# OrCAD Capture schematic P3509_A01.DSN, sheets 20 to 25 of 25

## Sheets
20 0005_SODIMM Connector 2_3: size Custom
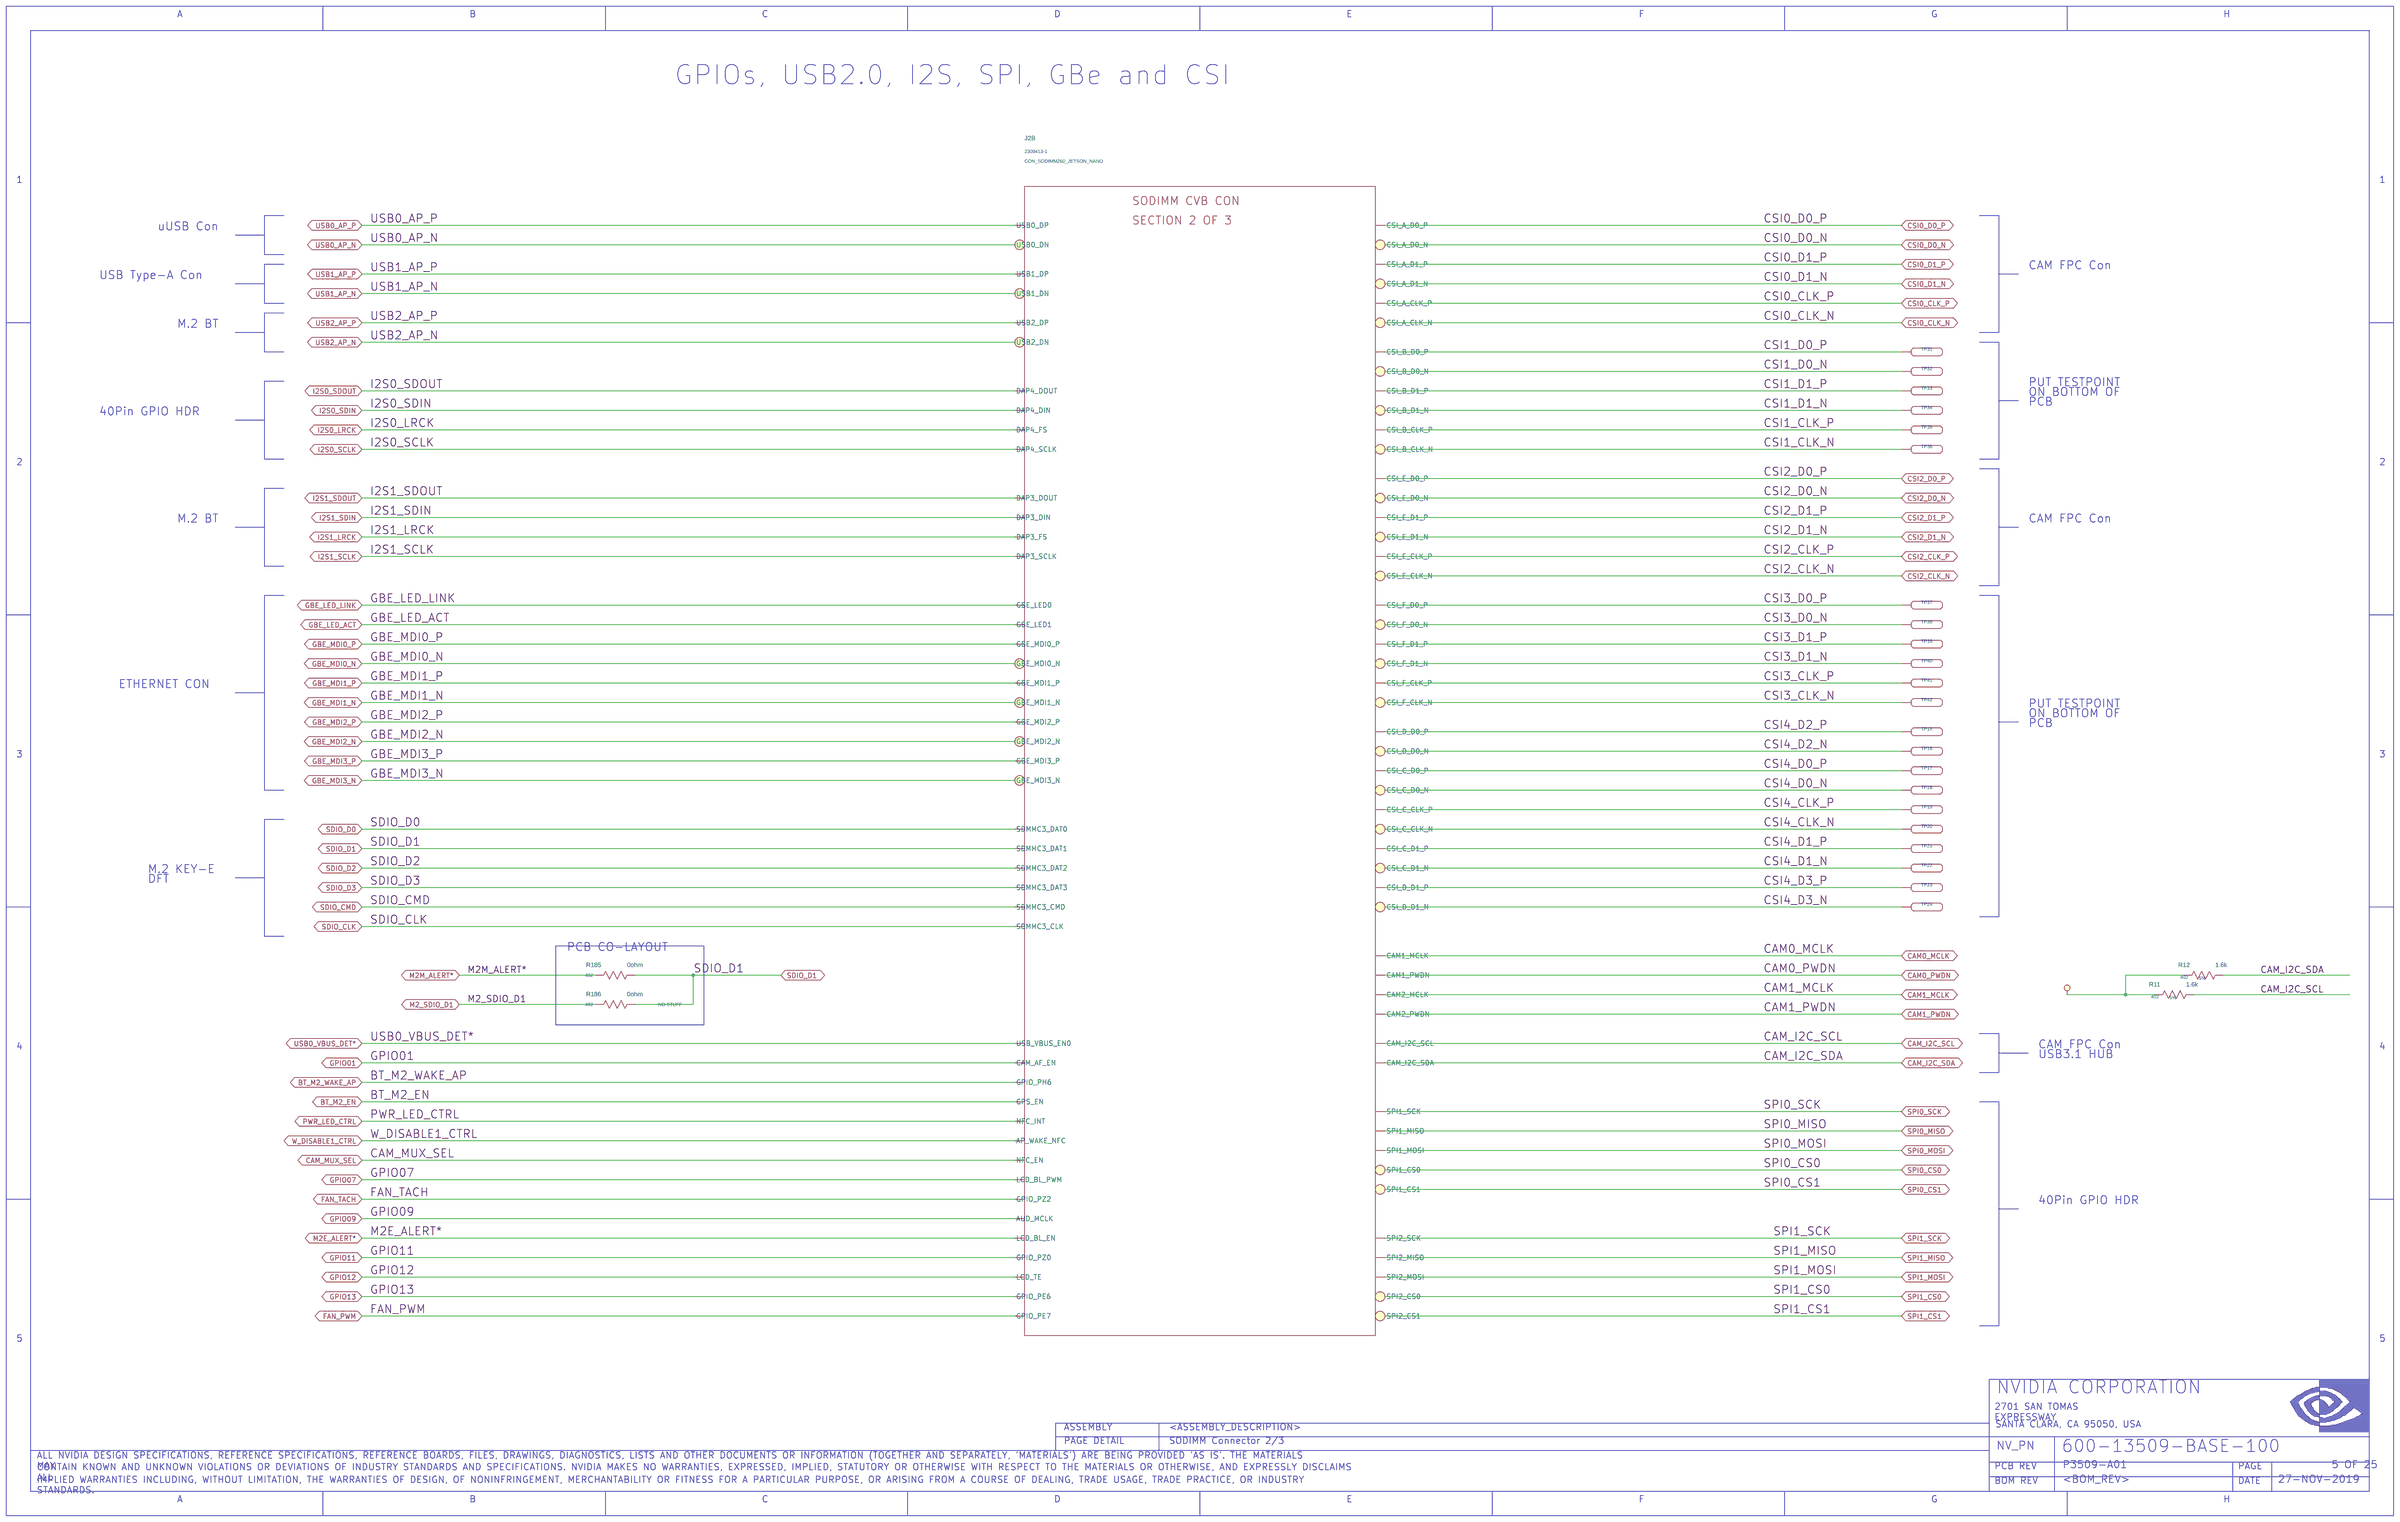
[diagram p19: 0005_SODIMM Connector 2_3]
21 0004_SODIMM Connector 1_3: size Custom
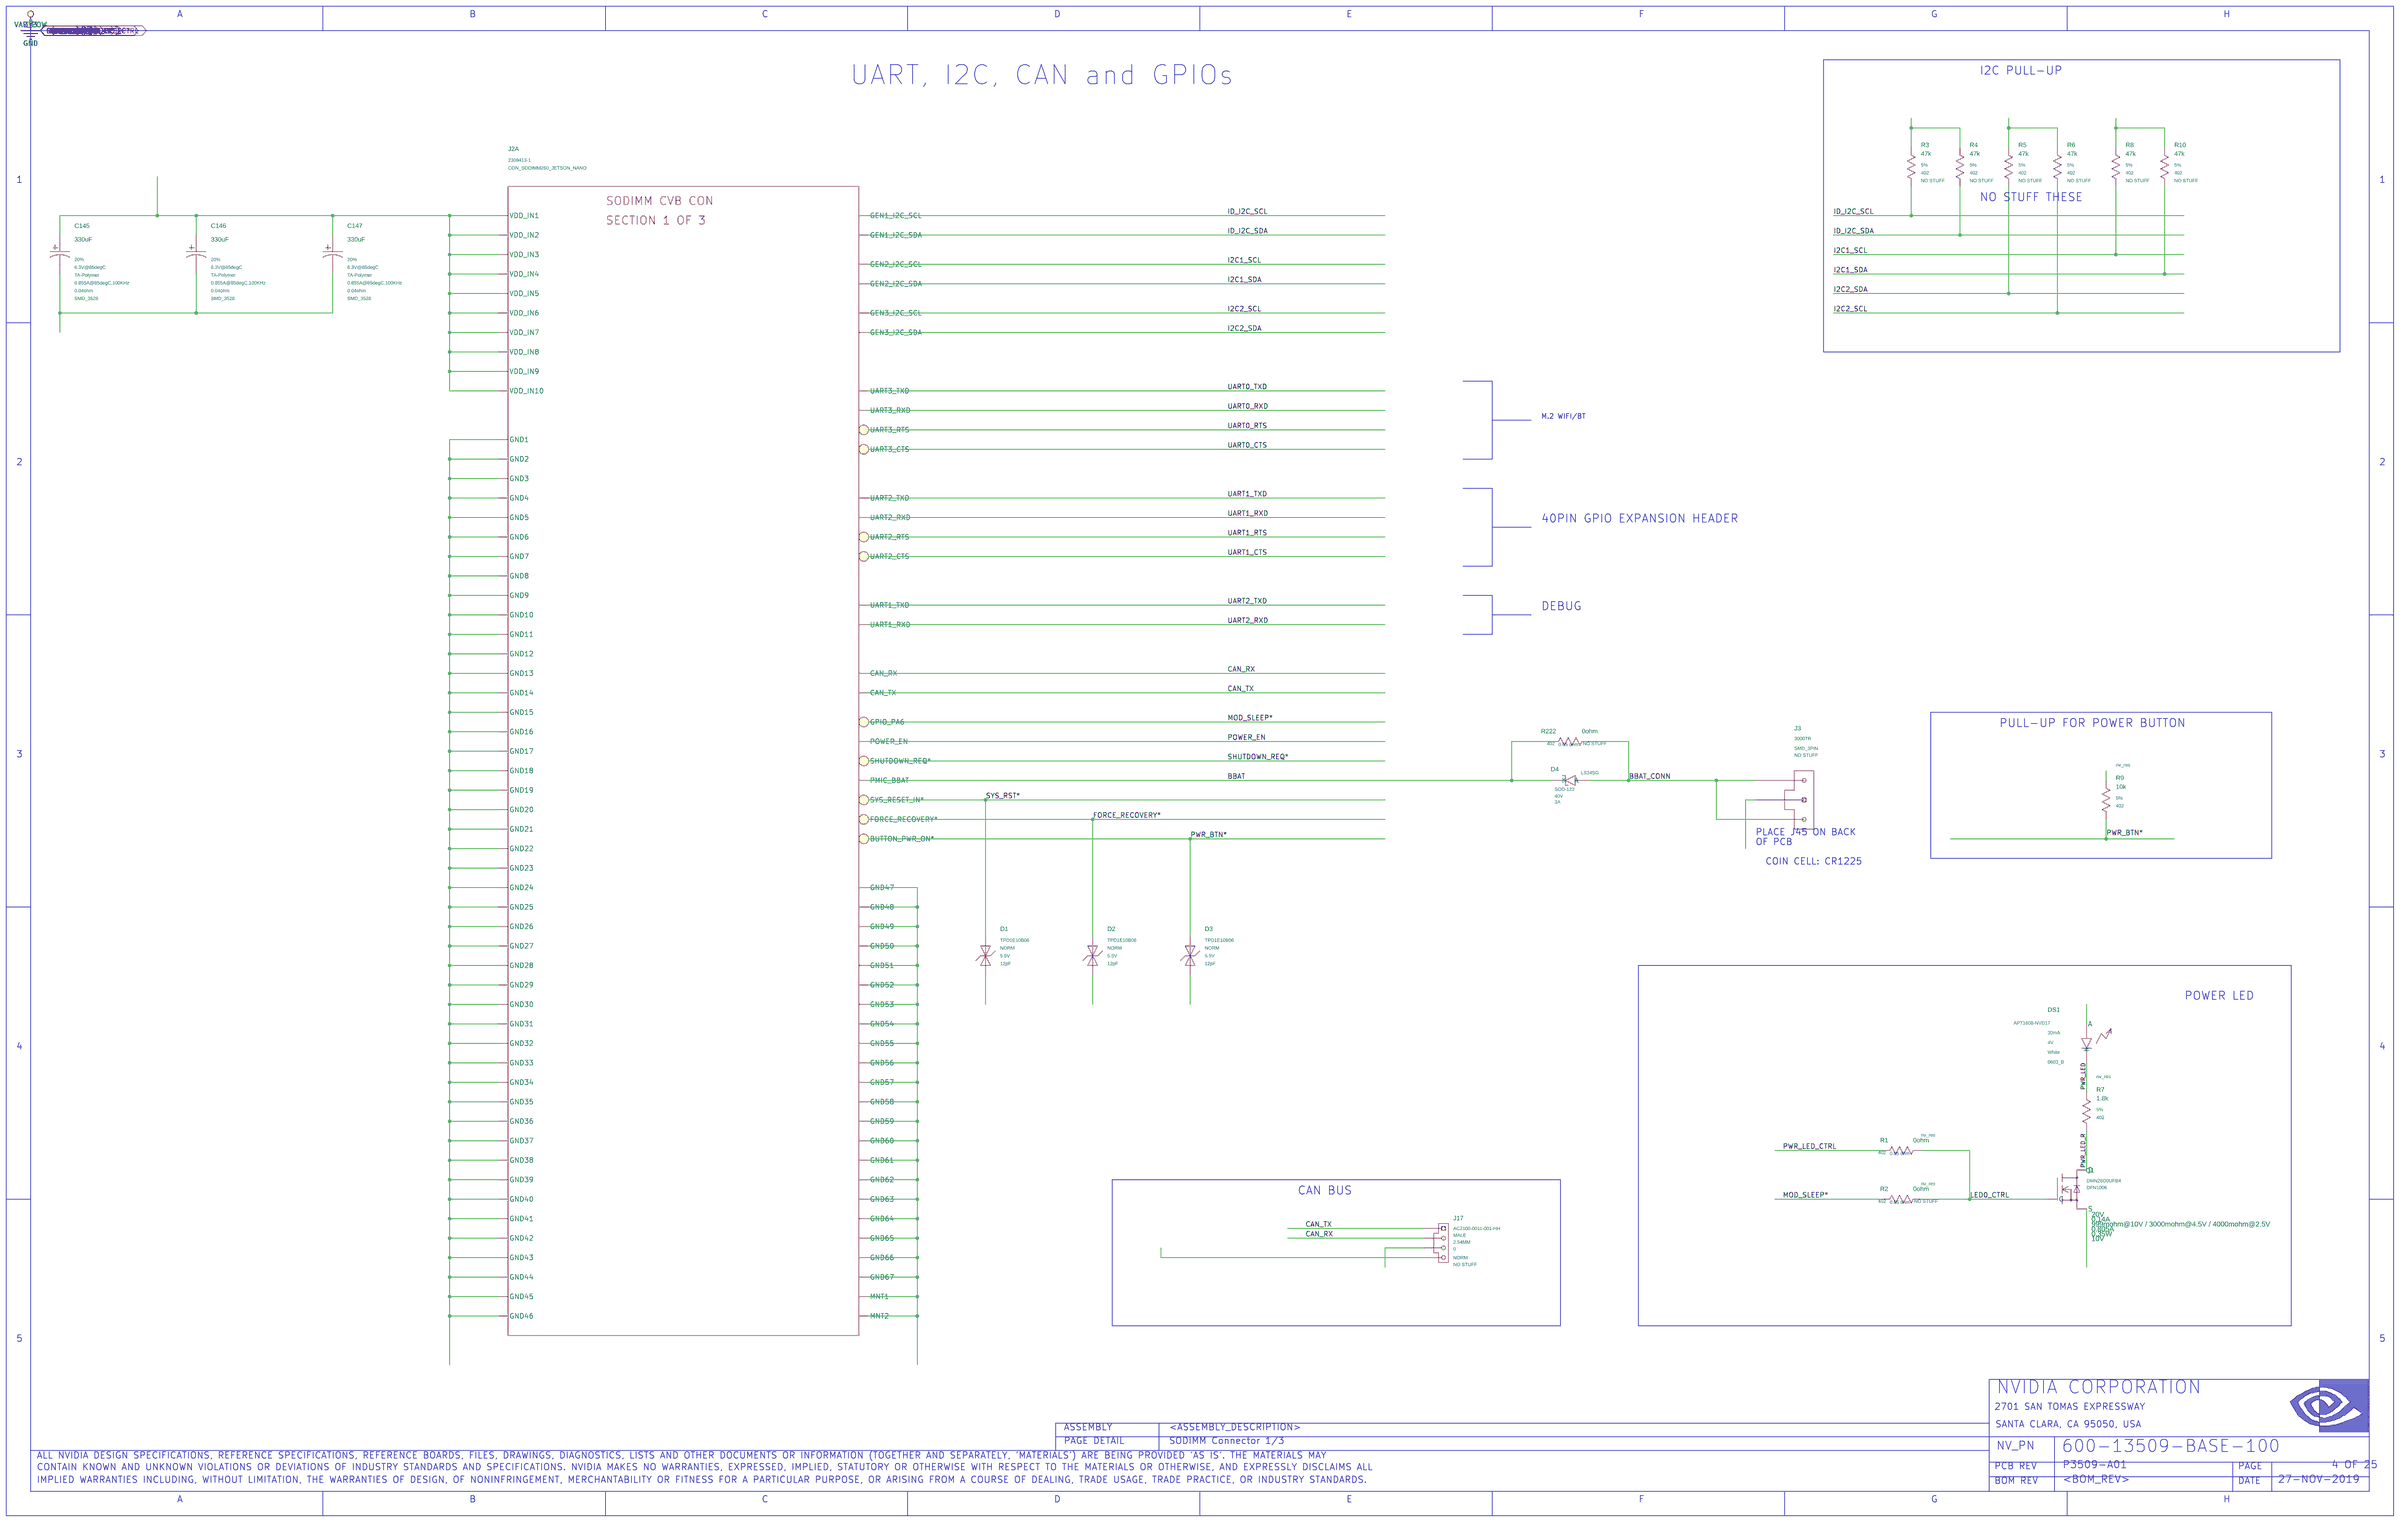
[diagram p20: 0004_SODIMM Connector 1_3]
22 0003_Power Tree
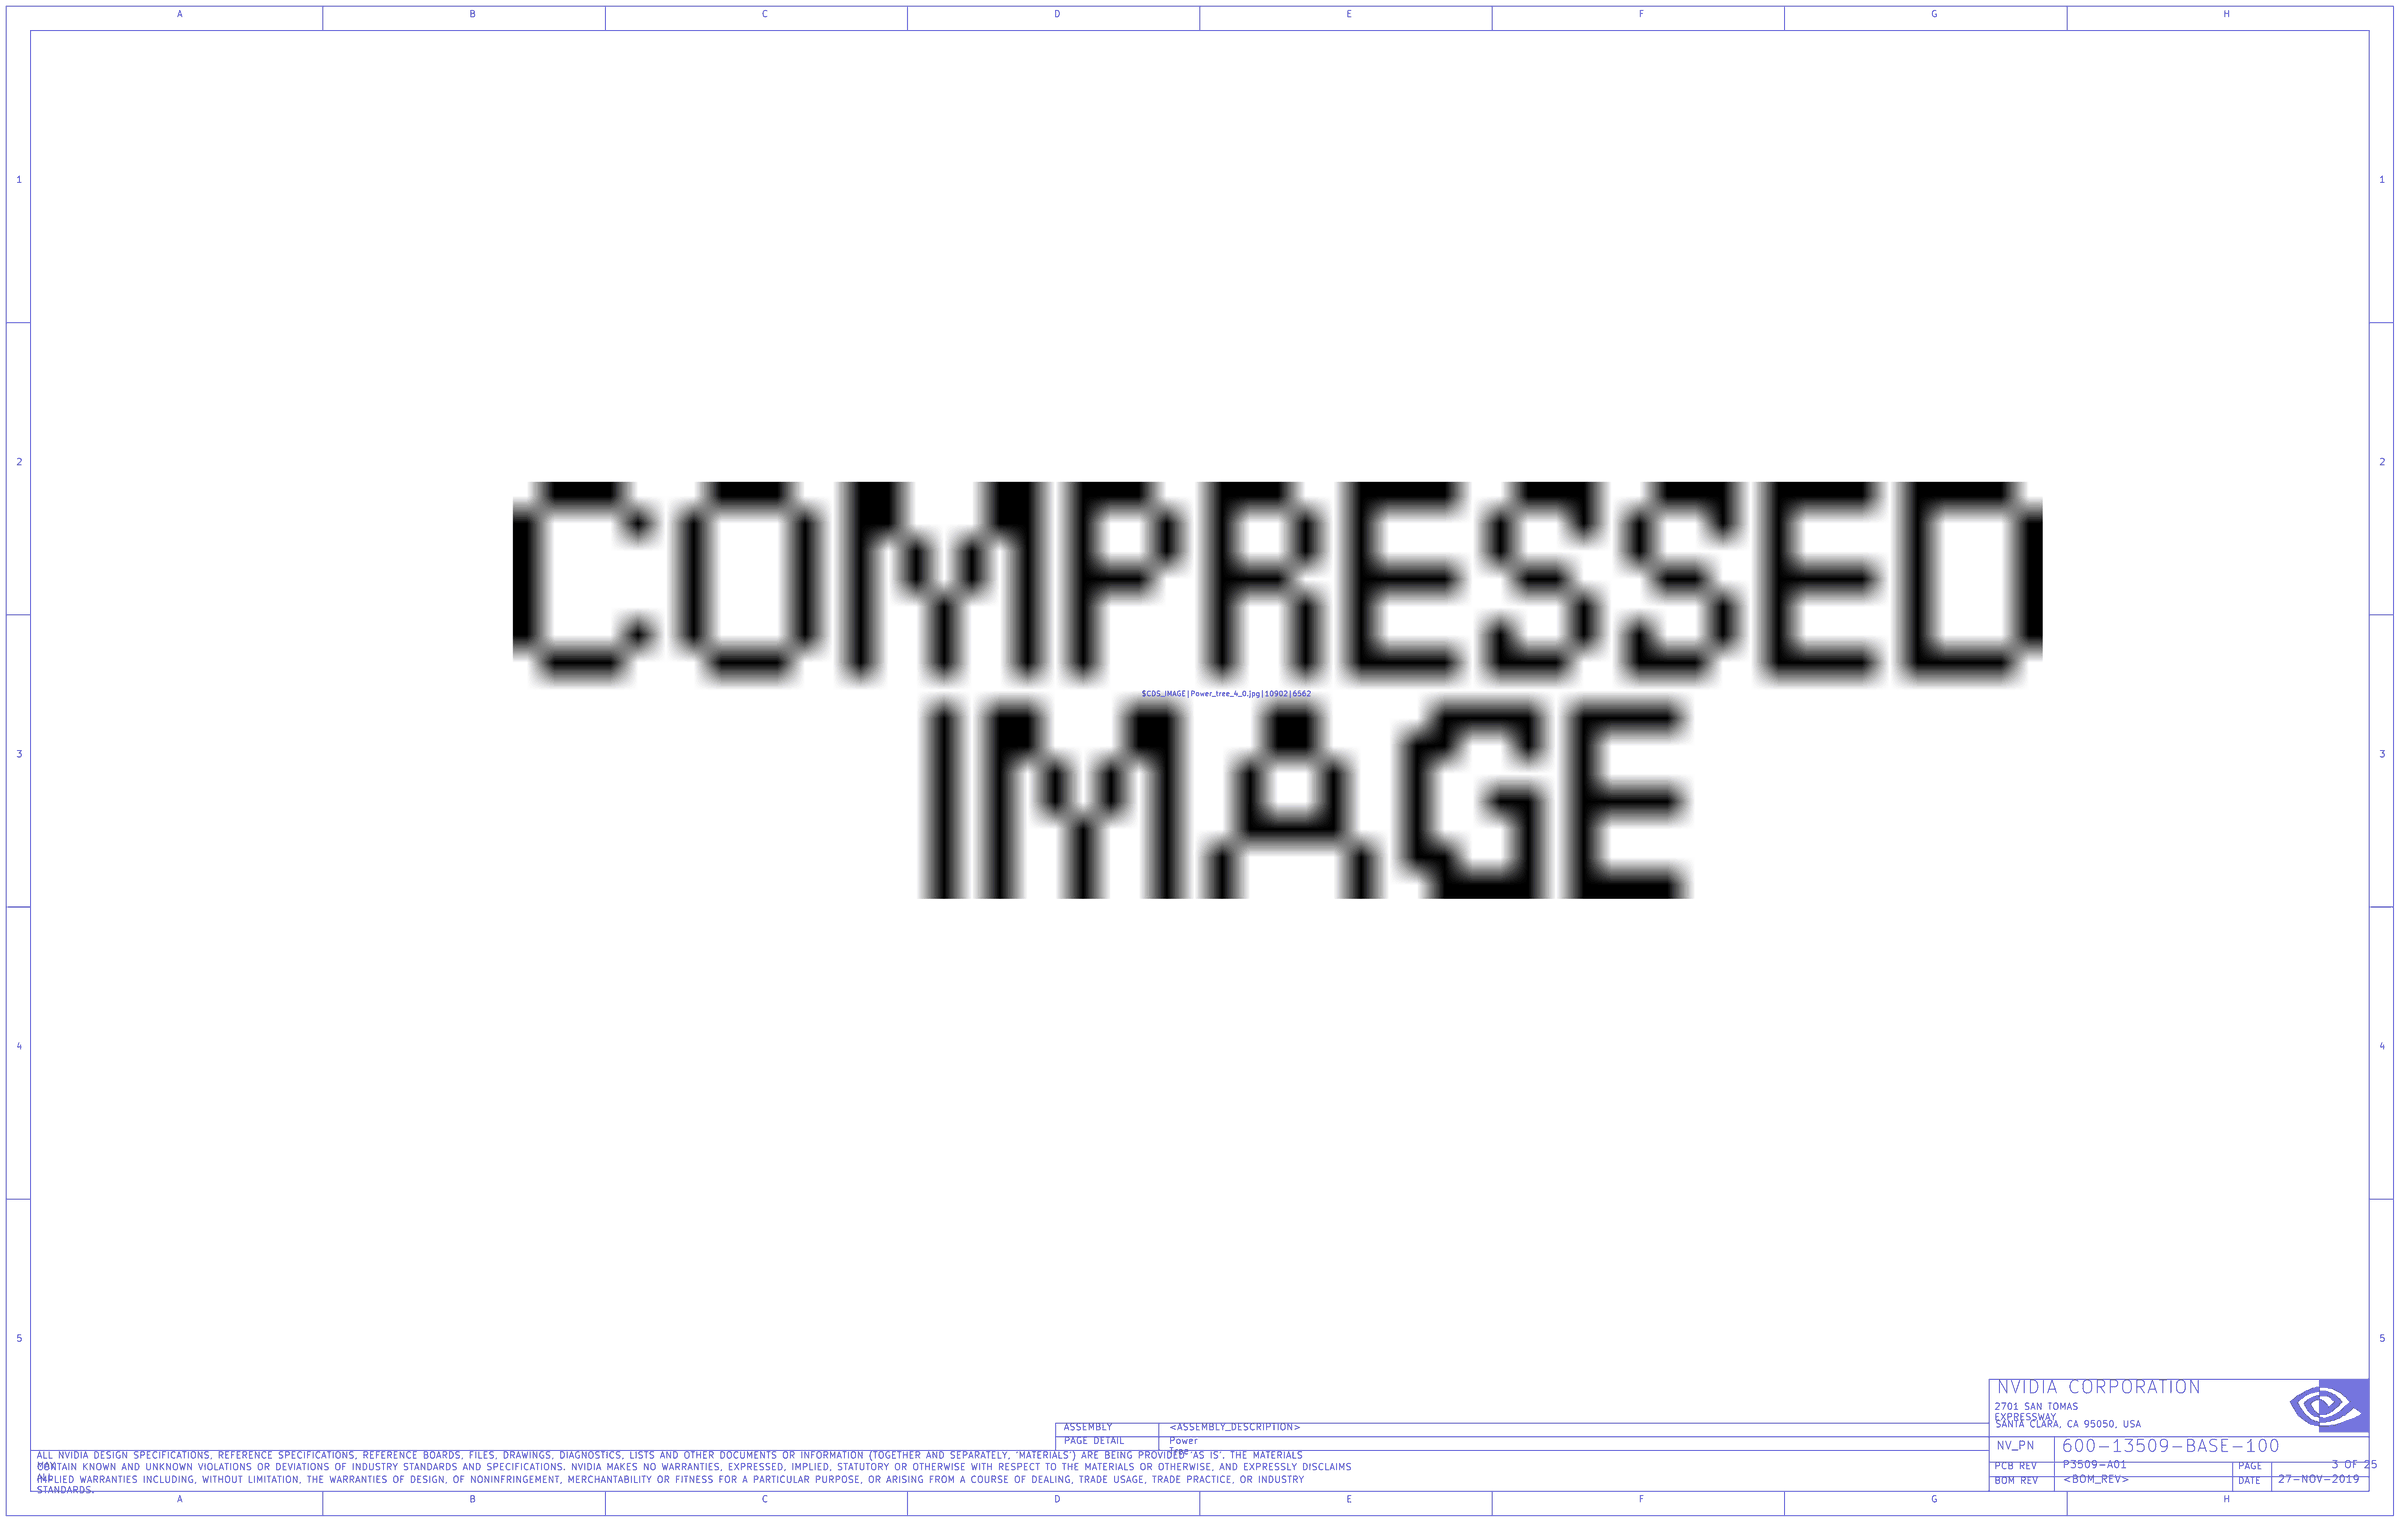
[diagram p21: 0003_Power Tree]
23 0002_Block Diagram
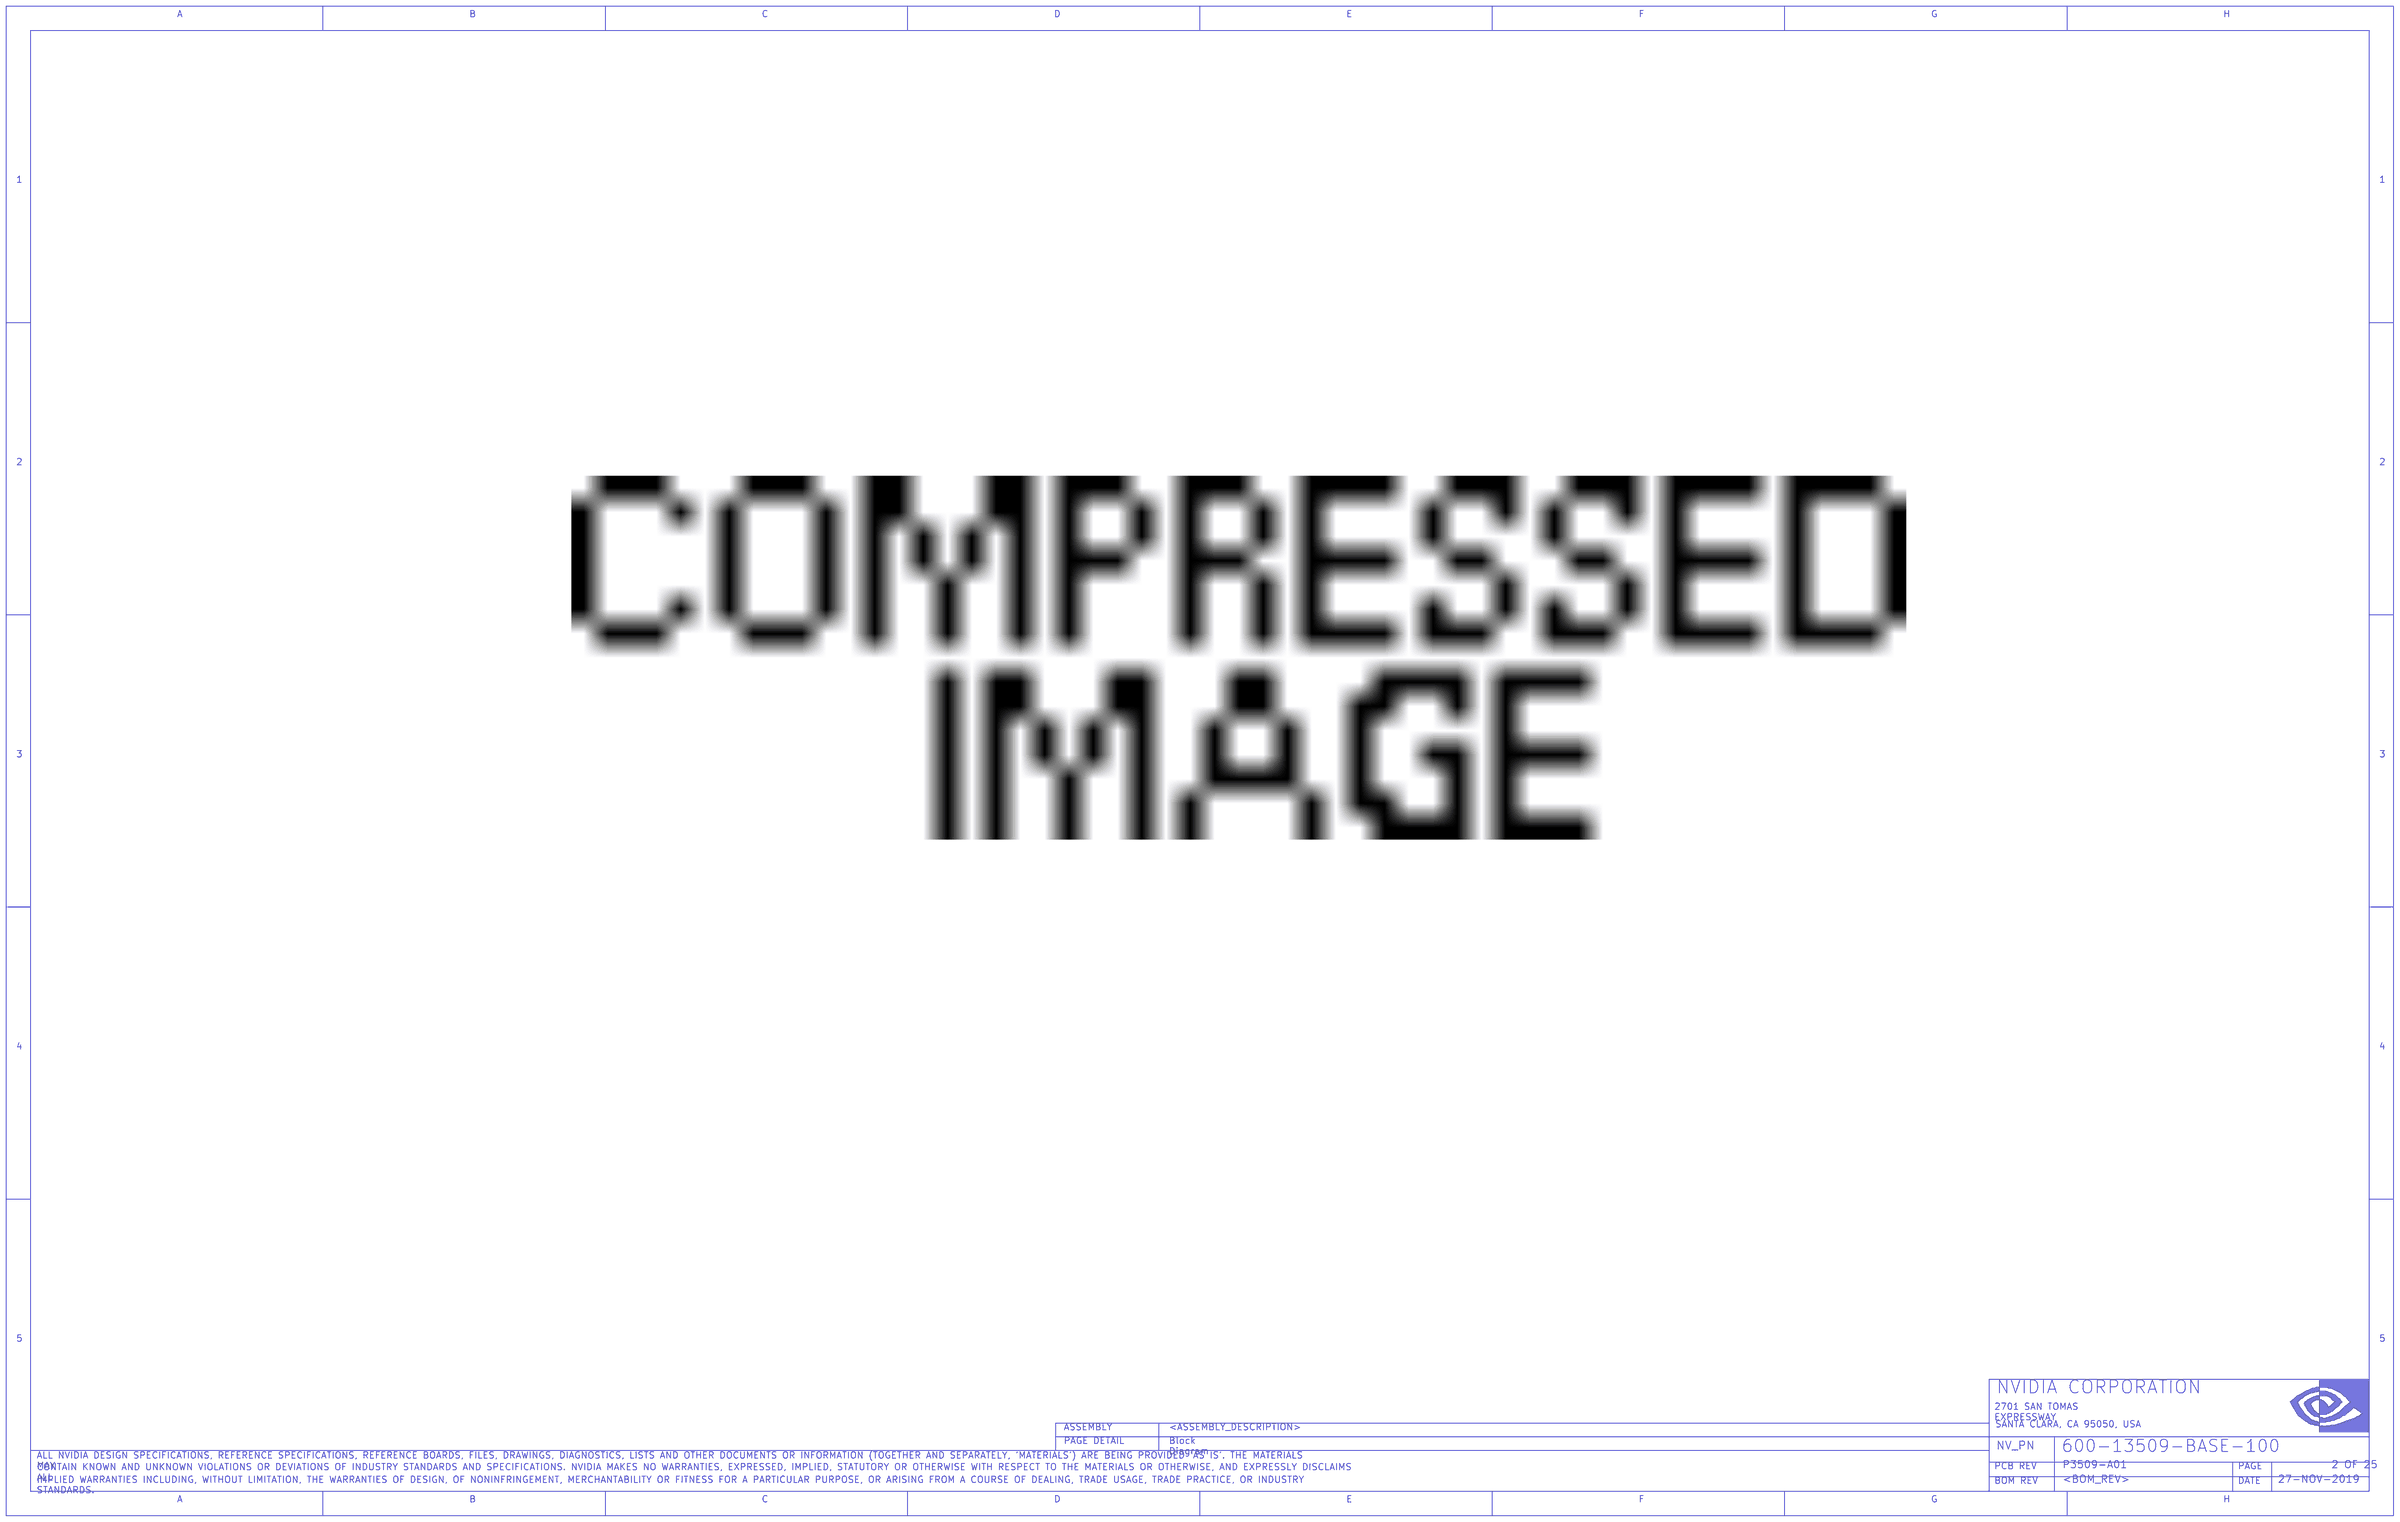
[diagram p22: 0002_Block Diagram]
24 0001_Table of Contents
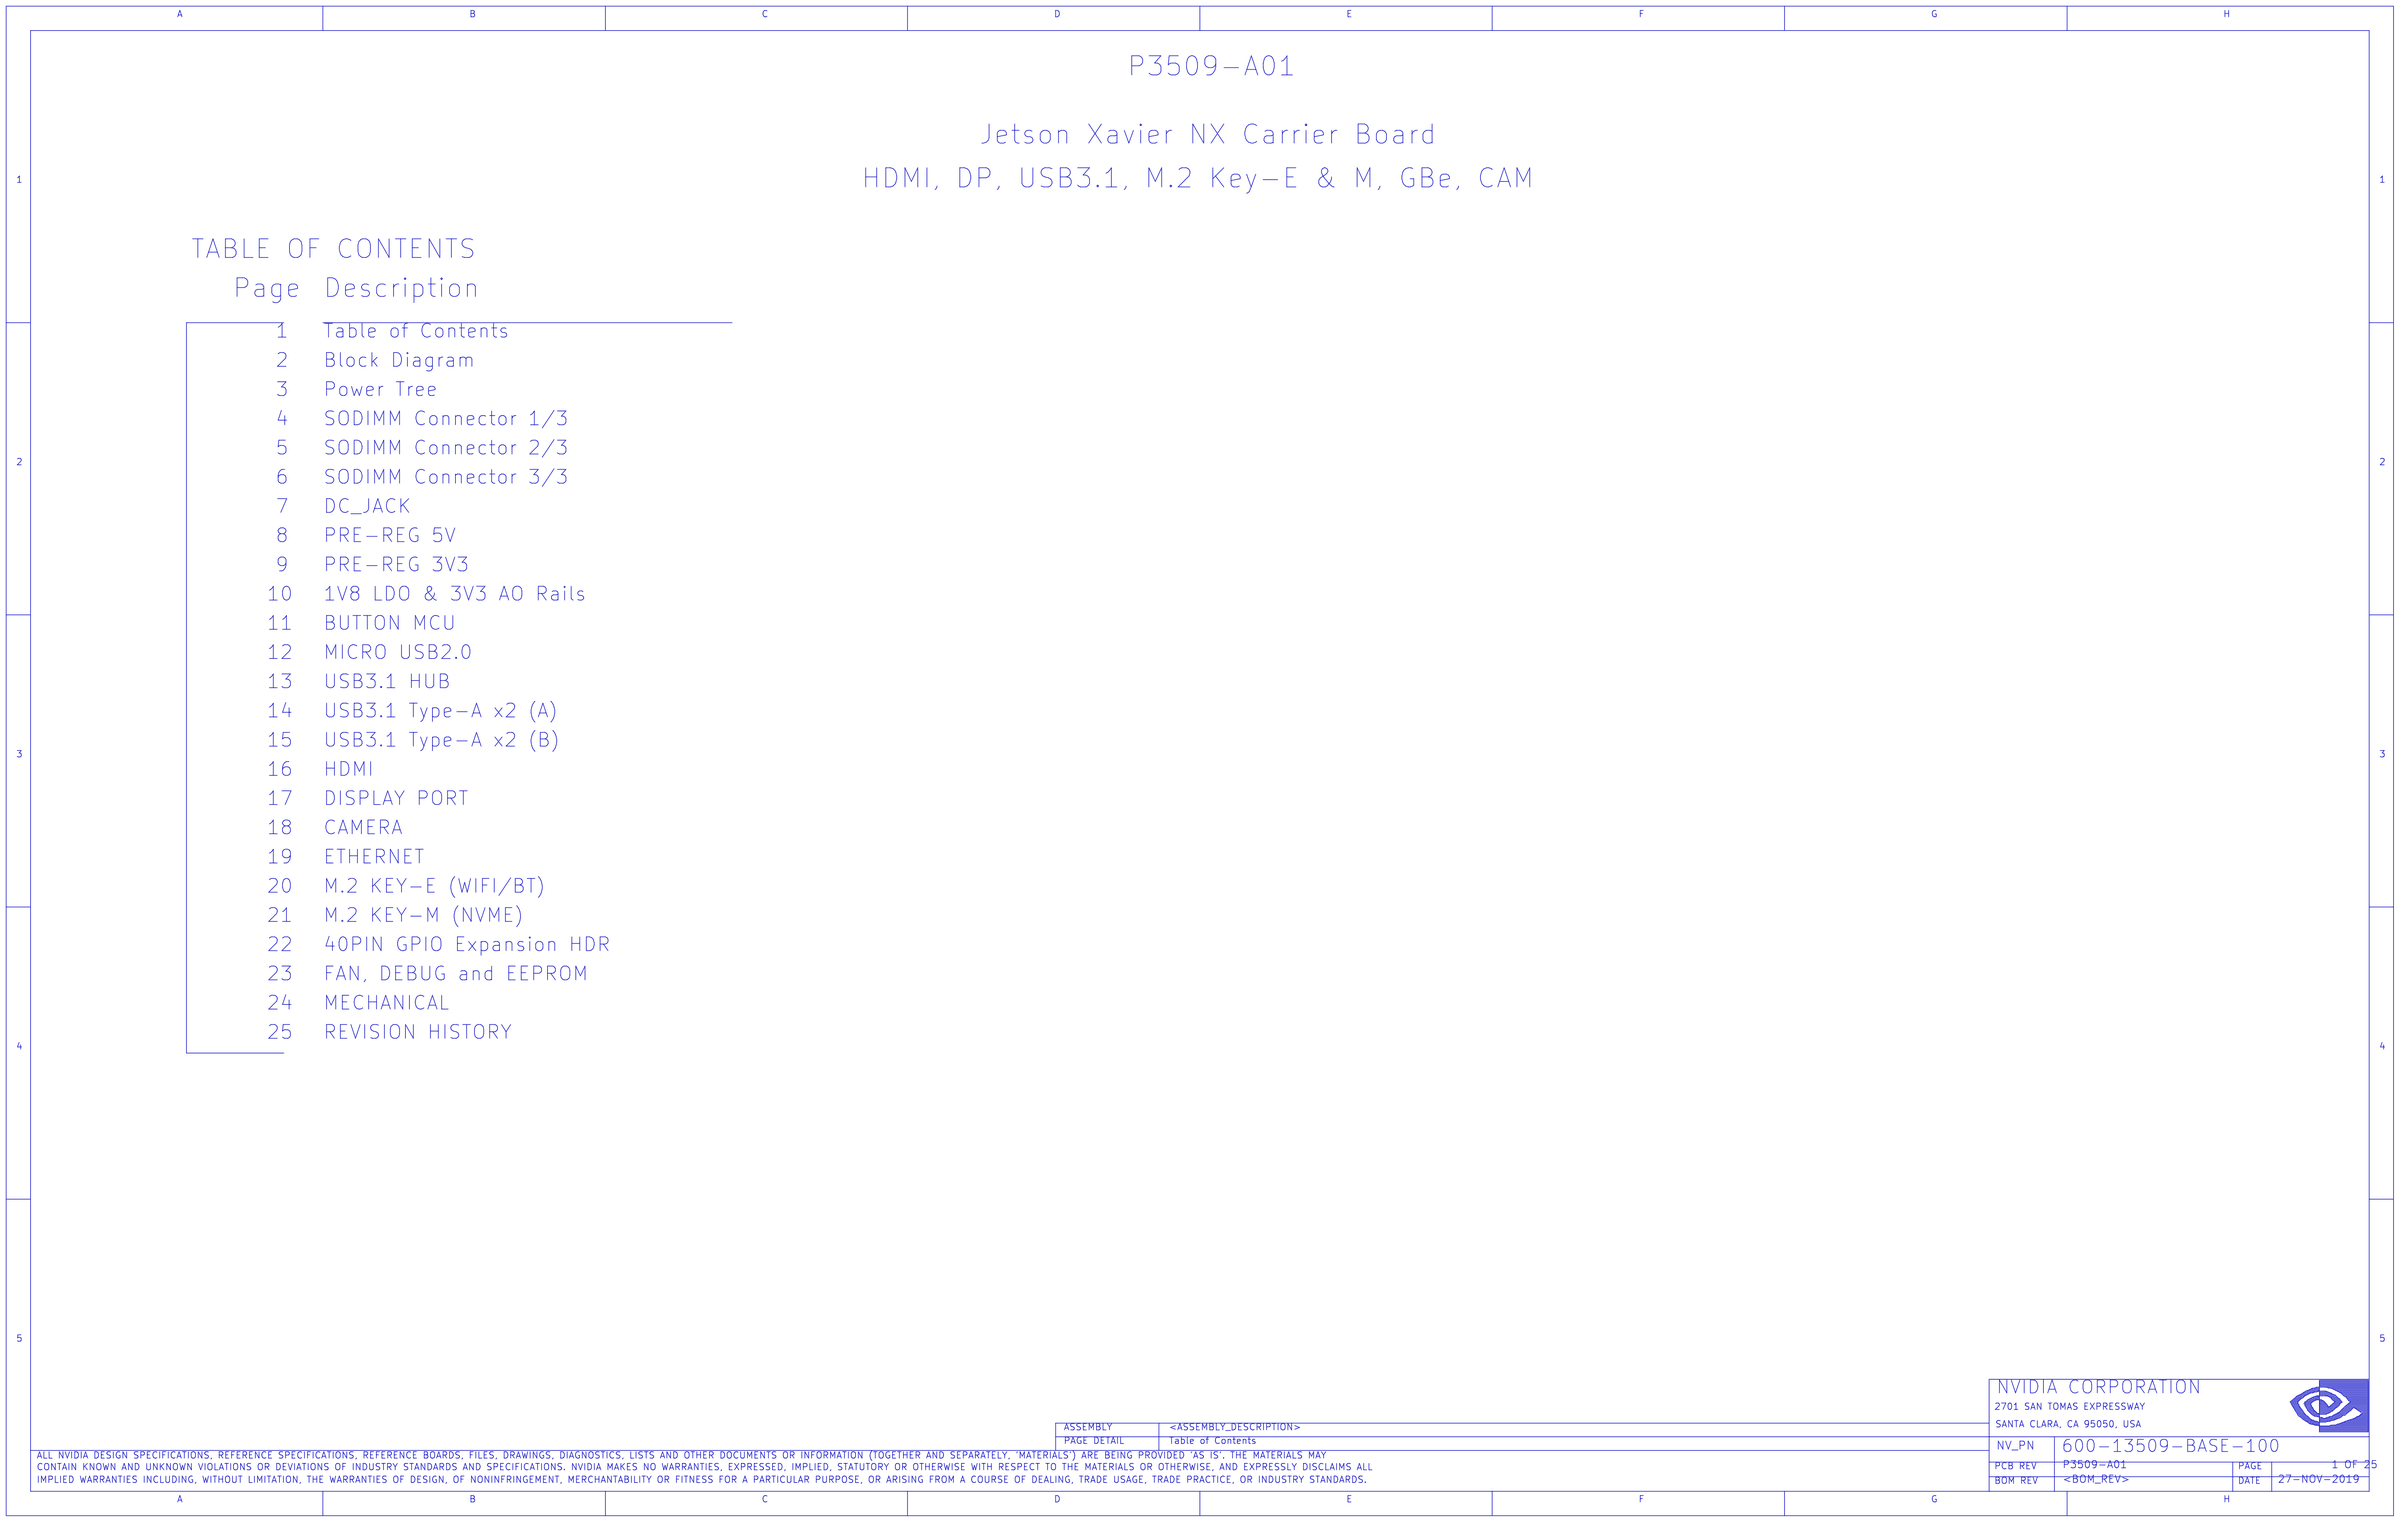
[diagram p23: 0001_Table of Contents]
25 0025_REVISION HISTORY
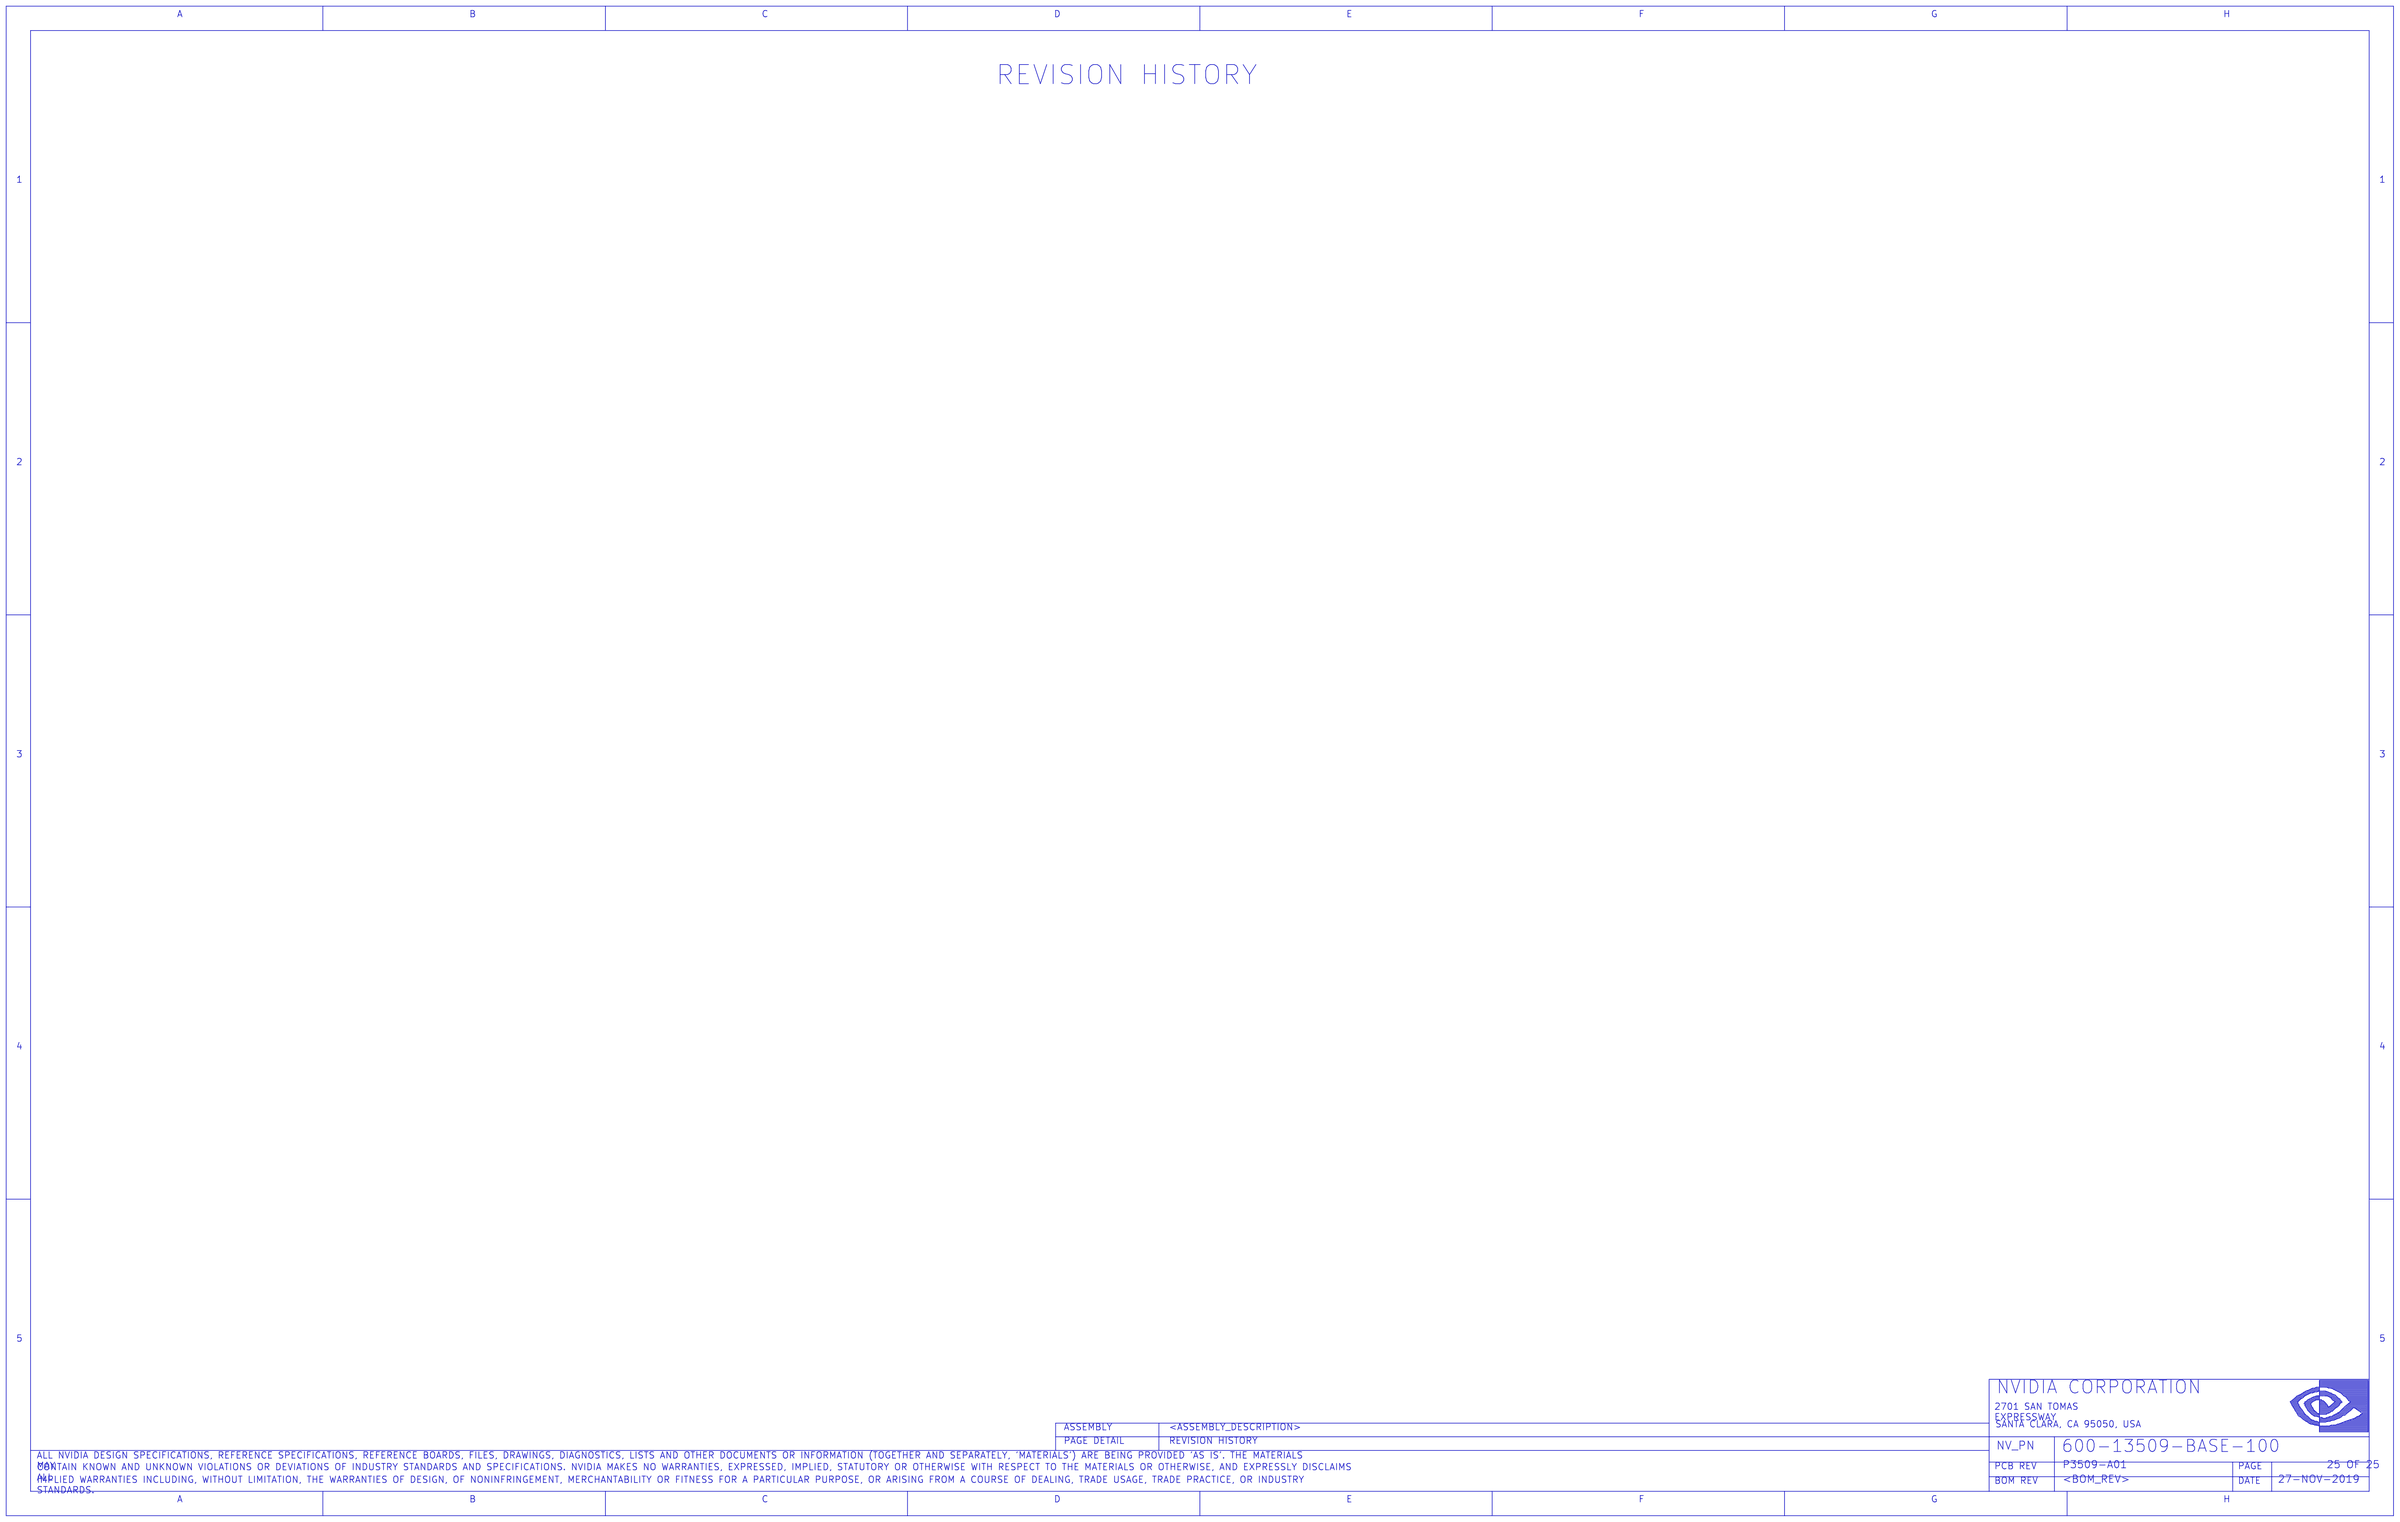
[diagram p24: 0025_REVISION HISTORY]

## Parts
sheet 0004_SODIMM Connector 1_3
C145  330uF  [CAP_SMD_3528]
C146  330uF  [CAP_SMD_3528]
C147  330uF  [CAP_SMD_3528]
D1  D_ESD  [DIODE_SMD_010X060]
D2  D_ESD  [DIODE_SMD_010X060]
D3  D_ESD  [DIODE_SMD_010X060]
D4  D_SCHOTTKY  [DIODE_SMD_SOD123]
DS1  LED  [LED_SMD_0603_ST_C]
J3  CON_BATTERY  [CON_BATTERY_003_SMD_ST_F_132X121]
J17  HDR_1X4  [CON_HDR_001X004_TH_RA_M_P025_B]
Q1  Q_FET_N_ENH  [DFET_003_SMD_010X006_B]
R1  0ohm  [402]
R2  0ohm  [402]
R3  47k  [402]
R4  47k  [402]
R5  47k  [402]
R6  47k  [402]
R7  1.8k  [402]
R8  47k  [402]
R9  10k  [402]
R10  47k  [402]
R222  0ohm  [402]
sheet 0005_SODIMM Connector 2_3
J2  CON_SODIMM_260  [CON_SODIMM_260_SMT_RA_F_P005]  (sections A,B,C)
R11  1.6k  [402]
R12  1.6k  [402]
R185  0ohm  [402]
R186  0ohm  [402]
TP15  LABTESTPOINT  [LTPB071C125D045C025P]
TP16  LABTESTPOINT  [LTPB071C125D045C025P]
TP17  LABTESTPOINT  [LTPB071C125D045C025P]
TP18  LABTESTPOINT  [LTPB071C125D045C025P]
TP19  LABTESTPOINT  [LTPB071C125D045C025P]
TP20  LABTESTPOINT  [LTPB071C125D045C025P]
TP21  LABTESTPOINT  [LTPB071C125D045C025P]
TP22  LABTESTPOINT  [LTPB071C125D045C025P]
TP23  LABTESTPOINT  [LTPB071C125D045C025P]
TP24  LABTESTPOINT  [LTPB071C125D045C025P]
TP31  LABTESTPOINT  [LTPB071C125D045C025P]
TP32  LABTESTPOINT  [LTPB071C125D045C025P]
TP33  LABTESTPOINT  [LTPB071C125D045C025P]
TP34  LABTESTPOINT  [LTPB071C125D045C025P]
TP35  LABTESTPOINT  [LTPB071C125D045C025P]
TP36  LABTESTPOINT  [LTPB071C125D045C025P]
TP37  LABTESTPOINT  [LTPB071C125D045C025P]
TP38  LABTESTPOINT  [LTPB071C125D045C025P]
TP39  LABTESTPOINT  [LTPB071C125D045C025P]
TP40  LABTESTPOINT  [LTPB071C125D045C025P]
TP41  LABTESTPOINT  [LTPB071C125D045C025P]
TP42  LABTESTPOINT  [LTPB071C125D045C025P]

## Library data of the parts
C145 = C_POL: ASSEMBLY: CVB_CONN; CDS_LIB: discrete; CDS_PART_NAME: C_POL_SMD_3528-330UF,TA-POLYMER,20%,6.3V@85DEGC,0.04OHM,9.999UH,0.855A@85DEGC,100KHZ,032-0696-000; CDS_PHYS_PART_NAME: C_POL_SMD_3528-330UF,TA-POLYMER,20%,6.3V@85DEGC,0.04OHM,9.999UH,0.855A@85DEGC,100KHZ,032-0696-000-032-0696-000,330UF; CDS_SEC: 1; DEVICE_TYPENAME: C_POL_SMD_3528-330UFTA-POLYMER2063V85DEGC004OHM9999UH0855A85DEGC100KHZ032-0696-000-032-0696-000330UF; DRAWING: #NAME?; ESL: 9.999uH; ESR: 0.04ohm; MAT: TA-Polymer; MAX_VOLTAGE: 6.3V@85degC; NV_PN: 032-0696-000; PACK_TYPE: SMD_3528; PATH: I82; PHYS_PAGE: 4; RIPPLE_CURRENT: 0.855A@85degC,100KHz; ROT: 0; SEC: 1; TOL: 20%; VER: 1; XY: (-11850,6350)
C146 = C_POL: ASSEMBLY: CVB_CONN; CDS_LIB: discrete; CDS_PART_NAME: C_POL_SMD_3528-330UF,TA-POLYMER,20%,6.3V@85DEGC,0.04OHM,9.999UH,0.855A@85DEGC,100KHZ,032-0696-000; CDS_PHYS_PART_NAME: C_POL_SMD_3528-330UF,TA-POLYMER,20%,6.3V@85DEGC,0.04OHM,9.999UH,0.855A@85DEGC,100KHZ,032-0696-000-032-0696-000,330UF; CDS_SEC: 1; DEVICE_TYPENAME: C_POL_SMD_3528-330UFTA-POLYMER2063V85DEGC004OHM9999UH0855A85DEGC100KHZ032-0696-000-032-0696-000330UF; DRAWING: #NAME?; ESL: 9.999uH; ESR: 0.04ohm; MAT: TA-Polymer; MAX_VOLTAGE: 6.3V@85degC; NV_PN: 032-0696-000; PACK_TYPE: SMD_3528; PATH: I83; PHYS_PAGE: 4; RIPPLE_CURRENT: 0.855A@85degC,100KHz; ROT: 0; SEC: 1; TOL: 20%; VER: 1; XY: (-11150,6350)
C147 = C_POL: ASSEMBLY: CVB_CONN; CDS_LIB: discrete; CDS_PART_NAME: C_POL_SMD_3528-330UF,TA-POLYMER,20%,6.3V@85DEGC,0.04OHM,9.999UH,0.855A@85DEGC,100KHZ,032-0696-000; CDS_PHYS_PART_NAME: C_POL_SMD_3528-330UF,TA-POLYMER,20%,6.3V@85DEGC,0.04OHM,9.999UH,0.855A@85DEGC,100KHZ,032-0696-000-032-0696-000,330UF; CDS_SEC: 1; DEVICE_TYPENAME: C_POL_SMD_3528-330UFTA-POLYMER2063V85DEGC004OHM9999UH0855A85DEGC100KHZ032-0696-000-032-0696-000330UF; DRAWING: #NAME?; ESL: 9.999uH; ESR: 0.04ohm; MAT: TA-Polymer; MAX_VOLTAGE: 6.3V@85degC; NV_PN: 032-0696-000; PACK_TYPE: SMD_3528; PATH: I84; PHYS_PAGE: 4; RIPPLE_CURRENT: 0.855A@85degC,100KHz; ROT: 0; SEC: 1; TOL: 20%; VER: 1; XY: (-10450,6350)
D1 = D_ESD: ASSEMBLY: CVB_CONN; BREAKDOWN_VOLTAGE_MIN_TYP: 6V; CAPACITANCE_MAX_TYP: 12pF; CDS_LIB: discrete; CDS_PART_NAME: D_ESD_NORM-TPD1E10B06,1 LINE,BI-DIRECTIONAL,5.5V,0.1UA,6V,10V@1A,12PF,090-0243-000; CDS_PHYS_PART_NAME: D_ESD_NORM-TPD1E10B06,1 LINE,BI-DIRECTIONAL,5.5V,0.1UA,6V,10V@1A,12PF,090-0243-000-090-0243-000; CDS_SEC: 1; CLAMPING_VOLTAGE: 10V@1A; CONFIGURATION: 1 Line; DEVICE_TYPENAME: D_ESD_NORM-TPD1E10B061LINEBI-DIRECTIONAL55V01UA6V10V1A12PF090-0243-000-090-0243-000; DRAWING: #NAME?; MAX_REVERSE_LEAKAGE_CURRENT: 0.1uA; MAX_REVERSE_VOLTAGE: 5.5V; NV_NAME: TPD1E10B06; NV_PN: 090-0243-000; PACK_TYPE: NORM; PATH: I54; PHYS_PAGE: 4; POLARITY: Bi-Directional; ROT: 0; SEC: 1; VER: 2; XY: (-7100,2750)
D2 = D_ESD: ASSEMBLY: CVB_CONN; BREAKDOWN_VOLTAGE_MIN_TYP: 6V; CAPACITANCE_MAX_TYP: 12pF; CDS_LIB: discrete; CDS_PART_NAME: D_ESD_NORM-TPD1E10B06,1 LINE,BI-DIRECTIONAL,5.5V,0.1UA,6V,10V@1A,12PF,090-0243-000; CDS_PHYS_PART_NAME: D_ESD_NORM-TPD1E10B06,1 LINE,BI-DIRECTIONAL,5.5V,0.1UA,6V,10V@1A,12PF,090-0243-000-090-0243-000; CDS_SEC: 1; CLAMPING_VOLTAGE: 10V@1A; CONFIGURATION: 1 Line; DEVICE_TYPENAME: D_ESD_NORM-TPD1E10B061LINEBI-DIRECTIONAL55V01UA6V10V1A12PF090-0243-000-090-0243-000; DRAWING: #NAME?; MAX_REVERSE_LEAKAGE_CURRENT: 0.1uA; MAX_REVERSE_VOLTAGE: 5.5V; NV_NAME: TPD1E10B06; NV_PN: 090-0243-000; PACK_TYPE: NORM; PATH: I53; PHYS_PAGE: 4; POLARITY: Bi-Directional; ROT: 0; SEC: 1; VER: 2; XY: (-6550,2750)
D3 = D_ESD: ASSEMBLY: CVB_CONN; BREAKDOWN_VOLTAGE_MIN_TYP: 6V; CAPACITANCE_MAX_TYP: 12pF; CDS_LIB: discrete; CDS_PART_NAME: D_ESD_NORM-TPD1E10B06,1 LINE,BI-DIRECTIONAL,5.5V,0.1UA,6V,10V@1A,12PF,090-0243-000; CDS_PHYS_PART_NAME: D_ESD_NORM-TPD1E10B06,1 LINE,BI-DIRECTIONAL,5.5V,0.1UA,6V,10V@1A,12PF,090-0243-000-090-0243-000; CDS_SEC: 1; CLAMPING_VOLTAGE: 10V@1A; CONFIGURATION: 1 Line; DEVICE_TYPENAME: D_ESD_NORM-TPD1E10B061LINEBI-DIRECTIONAL55V01UA6V10V1A12PF090-0243-000-090-0243-000; DRAWING: #NAME?; MAX_REVERSE_LEAKAGE_CURRENT: 0.1uA; MAX_REVERSE_VOLTAGE: 5.5V; NV_NAME: TPD1E10B06; NV_PN: 090-0243-000; PACK_TYPE: NORM; PATH: I51; PHYS_PAGE: 4; POLARITY: Bi-Directional; ROT: 0; SEC: 1; VER: 2; XY: (-6050,2750)
D4 = D_SCHOTTKY: ASSEMBLY: CVB_CONN; CDS_LIB: discrete; CDS_PART_NAME: D_SCHOTTKY_SOD-123-LS34SG,SINGLE,40V,25A,0.38V@1A,3A,090-0155-000; CDS_PHYS_PART_NAME: D_SCHOTTKY_SOD-123-LS34SG,SINGLE,40V,25A,0.38V@1A,3A,090-0155-000-090-0155-000; CDS_SEC: 1; CONFIGURATION: Single; CONTINUOUS_CURRENT: 3A; DEVICE_TYPENAME: D_SCHOTTKY_SOD-123-LS34SGSINGLE40V25A038V1A3A090-0155-000-090-0155-000; DRAWING: #NAME?; FORWARD_VOLTAGE: 0.38V@1A; MAX_CURRENT: 25A; MAX_VOLTAGE: 40V; NV_NAME: LS34SG; NV_PN: 090-0155-000; PACK_TYPE: SOD-123; PATH: I42; PHYS_PAGE: 4; PLACEMENT_NOTE: bottom side of pcb near J45; ROT: 0; SEC: 1; SEC_TYPE: SOD-123; VER: 1; XY: (-4100,3650)
DS1 = LED: ASSEMBLY: POWER_LED; CDS_LIB: discrete; CDS_PART_NAME: LED_0603_B-APT1608-NVD17,5V,0.15A,4V,30MA,WHITE,092-0160-000; CDS_PHYS_PART_NAME: LED_0603_B-APT1608-NVD17,5V,0.15A,4V,30MA,WHITE,092-0160-000-092-0160-000; CDS_SEC: 1; CONTINUOUS_CURRENT: 30mA; DEVICE_TYPENAME: LED_0603_B-APT1608-NVD175V015A4V30MAWHITE092-0160-000-092-0160-000; DRAWING: #NAME?; FORWARD_VOLTAGE: 4V; MAX_CURRENT: 0.15A; MAX_VOLTAGE: 5V; NV_COLOR: White; NV_NAME: APT1608-NVD17; NV_PN: 092-0160-000; PACK_TYPE: 0603_B; PATH: I21; PHYS_PAGE: 4; ROT: 0; SEC: 1; VER: 1; XY: (-1450,2300)
J3 = CON_BATTERY: ANGLE: N/A; ASSEMBLY: CVB_CONN; CDS_LIB: electro_mechanic; CDS_PART_NAME: CON_BATTERY_SMD_3PIN-3000TR,FEMALE,N/A,N/A,YES,NO,NO,NO,YES,N/A,N/A,220-0146-000; CDS_PHYS_PART_NAME: CON_BATTERY_SMD_3PIN-3000TR,FEMALE,N/A,N/A,YES,NO,NO,NO,YES,N/A,N/A,220-0146-000-220-0146-000; CDS_SEC: 1; DEVICE_TYPENAME: CON_BATTERY_SMD_3PIN-3000TRFEMALENANAYESNONONOYESNANA220-0146-000-220-0146-000; DRAWING: #NAME?; EMI_GROUND_TAB: NO; GENDER: FEMALE; LATCHING: NO; MAX_CURRENT: N/A; MAX_VOLTAGE: N/A; NV_NAME: 3000TR; NV_PN: 220-0146-000; PACK_TYPE: SMD_3PIN; PATH: I25; PHYS_PAGE: 4; PITCH: N/A; REFLOW: YES; ROT: 0; SEC: 1; SHIELDED: YES; SHROUDED: NO; SKU: NO STUFF; VER: 1; XY: (-2900,3550)
J17 = HDR_1X4: ANGLE: 0; ASSEMBLY: CVB_CONN; CDS_LIB: electro_mechanic; CDS_PART_NAME: HDR_1X4_NORM-AC2100-0011-001-HH,MALE,2.54MM,0,NO,N/A,NO,500VAC,3A,074-0245-000; CDS_PHYS_PART_NAME: HDR_1X4_NORM-AC2100-0011-001-HH,MALE,2.54MM,0,NO,N/A,NO,500VAC,3A,074-0245-000-074-0245-000; CDS_SEC: 1; DEVICE_TYPENAME: HDR_1X4_NORM-AC2100-0011-001-HHMALE254MM0NONANO500VAC3A074-0245-000-074-0245-000; DRAWING: #NAME?; GENDER: MALE; LATCHING: NO; MAX_CURRENT: 3A; MAX_VOLTAGE: 500VAC; NV_NAME: AC2100-0011-001-HH; NV_PN: 074-0245-000; PACK_TYPE: NORM; PATH: I93; PHYS_PAGE: 4; PITCH: 2.54MM; REFLOW: NO; ROT: 0; SEC: 1; SHROUDED: N/A; SKU: NO STUFF; VER: 1; XY: (-4750,1350)
Q1 = Q_FET_N_ENH#1: ASSEMBLY: POWER_LED; CDS_LIB: discrete; CDS_PART_NAME: Q_FET_N_ENH_DFN1006-DMN26D0UFB4,20V,999MOHM@10V / 3000MOHM@4.5V / 4000MOHM@2.5V,0.14A,0.805A,10V,0.35W,999NC@10V / 0NC@4.5V / A; CDS_PHYS_PART_NAME: Q_FET_N_ENH_DFN1006-DMN26D0UFB4,20V,999MOHM@10V / 3000MOHM@4.5V / 4000MOHM@2.5V,0.14A,0.805A,10V,0.35W,999NC@10V / 0NC@4.5V / B; CDS_SEC: 1; CONTINUOUS_CURRENT: 0.14A; CaptureCellPackProp: Q_FET_N_ENH##1; DEVICE_TYPENAME: Q_FET_N_ENH_DFN1006-DMN26D0UFB420V999MOHM10V3000MOHM45V4000MOHM25V014A0805A10V035W999NC10V0NC45VB; DRAWING: #NAME?; MAX_CURRENT: 0.805A; MAX_VOLTAGE: 20V; MAX_WATTAGE: 0.35W; NV_NAME: DMN26D0UFB4; NV_PN: 300-0868-000; PACK_TYPE: DFN1006; PATH: I23; PHYS_PAGE: 4; Q_G: 999nC@10V / 0nC@4.5V / 999nC@2.5V; ROT: 0; R_DS_ON: 999mohm@10V / 3000mohm@4.5V / 4000mohm@2.5V; SEC: 1; VER: 2; V_BE_GS: 10V; XY: (-1550,1550)
R1 = R#1: ASSEMBLY: POWER_LED; CDS_LIB: discrete; CDS_PART_NAME: R_0402-0OHM,0.05 OHM,62.5MW,195-2655-000; CDS_PHYS_PART_NAME: R_0402-0OHM,0.05 OHM,62.5MW,195-2655-000-0OHM,195-2655-000; CDS_SEC: 1; CHIPS_PART_NAME: R; DEVICE_TYPENAME: R_0402-0OHM005OHM625MW195-2655-000-0OHM195-2655-000; DRAWING: #NAME?; MAX_WATTAGE: 62.5mW; NV_PN: 195-2655-000; PATH: I28; PHYS_PAGE: 4; ROT: 0; SEC: 1; SIGNAL_MODEL: nv_res; TOL: 0.05 ohm; VER: 1; XY: (-2400,1750)
R2 = R#1: ASSEMBLY: POWER_LED; CDS_LIB: discrete; CDS_PART_NAME: R_0402-0OHM,0.05 OHM,62.5MW,195-2655-000; CDS_PHYS_PART_NAME: R_0402-0OHM,0.05 OHM,62.5MW,195-2655-000-0OHM,195-2655-000; CDS_SEC: 1; CHIPS_PART_NAME: R; DEVICE_TYPENAME: R_0402-0OHM005OHM625MW195-2655-000-0OHM195-2655-000; DRAWING: #NAME?; MAX_WATTAGE: 62.5mW; NV_PN: 195-2655-000; PATH: I27; PHYS_PAGE: 4; ROT: 0; SEC: 1; SIGNAL_MODEL: nv_res; SKU: NO STUFF; TOL: 0.05 ohm; VER: 1; XY: (-2400,1500)
R3 = R: ASSEMBLY: CVB_CONN; CDS_LIB: discrete; CDS_PART_NAME: R_0402-47K,5 %,62.5MW,195-0599-000; CDS_PHYS_PART_NAME: R_0402-47K,5 %,62.5MW,195-0599-000-195-0599-000,47K; CDS_SEC: 1; DEVICE_TYPENAME: R_0402-47K5625MW195-0599-000-195-0599-00047K; DRAWING: #NAME?; MAX_WATTAGE: 62.5mW; NV_PN: 195-0599-000; PATH: I16; PHYS_PAGE: 4; ROT: 0; SEC: 1; SIGNAL_MODEL: nv_res; SKU: NO STUFF; TOL: 5%; VER: 2; XY: (-2350,6800)
R4 = R: ASSEMBLY: CVB_CONN; CDS_LIB: discrete; CDS_PART_NAME: R_0402-47K,5 %,62.5MW,195-0599-000; CDS_PHYS_PART_NAME: R_0402-47K,5 %,62.5MW,195-0599-000-195-0599-000,47K; CDS_SEC: 1; DEVICE_TYPENAME: R_0402-47K5625MW195-0599-000-195-0599-00047K; DRAWING: #NAME?; MAX_WATTAGE: 62.5mW; NV_PN: 195-0599-000; PATH: I14; PHYS_PAGE: 4; ROT: 0; SEC: 1; SIGNAL_MODEL: nv_res; SKU: NO STUFF; TOL: 5%; VER: 2; XY: (-2100,6800)
R5 = R: ASSEMBLY: CVB_CONN; CDS_LIB: discrete; CDS_PART_NAME: R_0402-47K,5 %,62.5MW,195-0599-000; CDS_PHYS_PART_NAME: R_0402-47K,5 %,62.5MW,195-0599-000-195-0599-000,47K; CDS_SEC: 1; DEVICE_TYPENAME: R_0402-47K5625MW195-0599-000-195-0599-00047K; DRAWING: #NAME?; MAX_WATTAGE: 62.5mW; NV_PN: 195-0599-000; PATH: I12; PHYS_PAGE: 4; ROT: 0; SEC: 1; SIGNAL_MODEL: nv_res; SKU: NO STUFF; TOL: 5%; VER: 2; XY: (-1850,6800)
R6 = R: ASSEMBLY: CVB_CONN; CDS_LIB: discrete; CDS_PART_NAME: R_0402-47K,5 %,62.5MW,195-0599-000; CDS_PHYS_PART_NAME: R_0402-47K,5 %,62.5MW,195-0599-000-195-0599-000,47K; CDS_SEC: 1; DEVICE_TYPENAME: R_0402-47K5625MW195-0599-000-195-0599-00047K; DRAWING: #NAME?; MAX_WATTAGE: 62.5mW; NV_PN: 195-0599-000; PATH: I10; PHYS_PAGE: 4; ROT: 0; SEC: 1; SIGNAL_MODEL: nv_res; SKU: NO STUFF; TOL: 5%; VER: 2; XY: (-1600,6800)
R7 = R: ASSEMBLY: POWER_LED; CDS_LIB: discrete; CDS_PART_NAME: R_0402-1.8K,5 %,62.5MW,195-0528-000; CDS_PHYS_PART_NAME: R_0402-1.8K,5 %,62.5MW,195-0528-000-1.8K,195-0528-000; CDS_SEC: 1; DEVICE_TYPENAME: R_0402-18K5625MW195-0528-000-18K195-0528-000; DRAWING: #NAME?; MAX_WATTAGE: 62.5mW; NV_PN: 195-0528-000; PATH: I22; PHYS_PAGE: 4; ROT: 0; SEC: 1; SIGNAL_MODEL: nv_res; TOL: 5%; VER: 2; XY: (-1450,1950)
R8 = R: ASSEMBLY: CVB_CONN; CDS_LIB: discrete; CDS_PART_NAME: R_0402-47K,5 %,62.5MW,195-0599-000; CDS_PHYS_PART_NAME: R_0402-47K,5 %,62.5MW,195-0599-000-195-0599-000,47K; CDS_SEC: 1; DEVICE_TYPENAME: R_0402-47K5625MW195-0599-000-195-0599-00047K; DRAWING: #NAME?; MAX_WATTAGE: 62.5mW; NV_PN: 195-0599-000; PATH: I4; PHYS_PAGE: 4; ROT: 0; SEC: 1; SIGNAL_MODEL: nv_res; SKU: NO STUFF; TOL: 5%; VER: 2; XY: (-1300,6800)
R9 = R: ASSEMBLY: CVB_CONN; CDS_LIB: discrete; CDS_PART_NAME: R_0402-10K,5 %,62.5MW,195-0486-000; CDS_PHYS_PART_NAME: R_0402-10K,5 %,62.5MW,195-0486-000-10K,195-0486-000; CDS_SEC: 1; DEVICE_TYPENAME: R_0402-10K5625MW195-0486-000-10K195-0486-000; DRAWING: #NAME?; MAX_WATTAGE: 62.5mW; NV_PN: 195-0486-000; PATH: I19; PHYS_PAGE: 4; ROT: 0; SEC: 1; SIGNAL_MODEL: nv_res; TOL: 5%; VER: 2; XY: (-1350,3550)
R10 = R: ASSEMBLY: CVB_CONN; CDS_LIB: discrete; CDS_PART_NAME: R_0402-47K,5 %,62.5MW,195-0599-000; CDS_PHYS_PART_NAME: R_0402-47K,5 %,62.5MW,195-0599-000-195-0599-000,47K; CDS_SEC: 1; DEVICE_TYPENAME: R_0402-47K5625MW195-0599-000-195-0599-00047K; DRAWING: #NAME?; MAX_WATTAGE: 62.5mW; NV_PN: 195-0599-000; PATH: I2; PHYS_PAGE: 4; ROT: 0; SEC: 1; SIGNAL_MODEL: nv_res; SKU: NO STUFF; TOL: 5%; VER: 2; XY: (-1050,6800)
R222 = R#1: ASSEMBLY: CVB_CONN; CDS_LIB: discrete; CDS_PART_NAME: R_0402-0OHM,0.05 OHM,62.5MW,195-2655-000; CDS_PHYS_PART_NAME: R_0402-0OHM,0.05 OHM,62.5MW,195-2655-000-0OHM,195-2655-000; CDS_SEC: 1; CHIPS_PART_NAME: R; DEVICE_TYPENAME: R_0402-0OHM005OHM625MW195-2655-000-0OHM195-2655-000; DRAWING: #NAME?; MAX_WATTAGE: 62.5mW; NV_PN: 195-2655-000; PATH: I94; PHYS_PAGE: 4; ROT: 0; SEC: 1; SKU: NO STUFF; TOL: 0.05 ohm; VER: 1; XY: (-4100,3850)
J2 = CON_SODIMM_260: ANGLE: 90; ASSEMBLY: CVB_CONN; CDS_LIB: electro_mechanic; CDS_PART_NAME: CON_SODIMM_260_CON_SODIMM260_JETSON_NANO-2309413-1,FEMALE,0.5MM,90,N/A,N/A,YES,NO,NO,25 V,0.5 A,080-1656-000; CDS_PHYS_PART_NAME: CON_SODIMM_260_CON_SODIMM260_JETSON_NANO-2309413-1,FEMALE,0.5MM,90,N/A,N/A,YES,NO,NO,25 V,0.5 A,080-1656-000-080-1656-000; CDS_SEC: 1; CaptureCellPackProp: CON_SODIMM_260A; DEVICE_TYPENAME: CON_SODIMM_260_CON_SODIMM260_JETSON_NANO-2309413-1FEMALE05MM90NANAYESNONO25V05A080-1656-000-080-1656-000; DRAWING: #NAME?; EMI_GROUND_TAB: NO; GENDER: FEMALE; LATCHING: YES; MAX_CURRENT: 0.5 A; MAX_VOLTAGE: 25 V; NV_NAME: 2309413-1; NV_PN: 080-1656-000; PACK_TYPE: CON_SODIMM260_JETSON_NANO; PATH: I62; PHYS_PAGE: 4; PITCH: 0.5mm; REFLOW: N/A; ROT: 0; SEC: 1; SHIELDED: NO; SHROUDED: N/A; VER: 5; XY: (-8650,3750)
R11 = R#1: ASSEMBLY: CVB_CONN; CDS_LIB: discrete; CDS_PART_NAME: R_0402-1.6K,5 %,62.5MW,195-0521-000; CDS_PHYS_PART_NAME: R_0402-1.6K,5 %,62.5MW,195-0521-000-1.6K,195-0521-000; CDS_SEC: 1; CHIPS_PART_NAME: R; DEVICE_TYPENAME: R_0402-16K5625MW195-0521-000-16K195-0521-000; DRAWING: #NAME?; MAX_WATTAGE: 62.5mW; NV_PN: 195-0521-000; PATH: I130; PHYS_PAGE: 5; ROT: 0; SEC: 1; SIGNAL_MODEL: nv_res; TOL: 5%; VER: 1; XY: (-1000,2550)
R12 = R#1: ASSEMBLY: CVB_CONN; CDS_LIB: discrete; CDS_PART_NAME: R_0402-1.6K,5 %,62.5MW,195-0521-000; CDS_PHYS_PART_NAME: R_0402-1.6K,5 %,62.5MW,195-0521-000-1.6K,195-0521-000; CDS_SEC: 1; CHIPS_PART_NAME: R; DEVICE_TYPENAME: R_0402-16K5625MW195-0521-000-16K195-0521-000; DRAWING: #NAME?; MAX_WATTAGE: 62.5mW; NV_PN: 195-0521-000; PATH: I129; PHYS_PAGE: 5; ROT: 0; SEC: 1; SIGNAL_MODEL: nv_res; TOL: 5%; VER: 1; XY: (-850,2650)
R185 = R#1: ASSEMBLY: M2_NVME; CDS_LIB: discrete; CDS_PART_NAME: R_0402-0OHM,0.05 OHM,62.5MW,195-2655-000; CDS_PHYS_PART_NAME: R_0402-0OHM,0.05 OHM,62.5MW,195-2655-000-0OHM,195-2655-000; CDS_SEC: 1; CHIPS_PART_NAME: R; DEVICE_TYPENAME: R_0402-0OHM005OHM625MW195-2655-000-0OHM195-2655-000; DRAWING: #NAME?; MAX_WATTAGE: 62.5mW; NV_PN: 195-2655-000; PATH: I190; PHYS_PAGE: 5; ROT: 0; SEC: 1; TOL: 0.05 ohm; VER: 1; XY: (-9000,2650)
R186 = R#1: ASSEMBLY: M2_WIFIBT; CDS_LIB: discrete; CDS_PART_NAME: R_0402-0OHM,0.05 OHM,62.5MW,195-2655-000; CDS_PHYS_PART_NAME: R_0402-0OHM,0.05 OHM,62.5MW,195-2655-000-0OHM,195-2655-000; CDS_SEC: 1; CHIPS_PART_NAME: R; DEVICE_TYPENAME: R_0402-0OHM005OHM625MW195-2655-000-0OHM195-2655-000; DRAWING: #NAME?; MAX_WATTAGE: 62.5mW; NV_PN: 195-2655-000; PATH: I189; PHYS_PAGE: 5; ROT: 0; SEC: 1; SKU: NO STUFF; TOL: 0.05 ohm; VER: 1; XY: (-9000,2500)
TP15 = LABTESTPOINT: CDS_LIB: electro_mechanic; CDS_PART_NAME: LABTESTPOINT_PIN-LTPB071C125; CDS_PHYS_PART_NAME: LABTESTPOINT_PIN-LTPB071C125; CDS_SEC: 1; DEVICE_TYPENAME: LABTESTPOINT_PIN-LTPB071C125; DRAWING: #NAME?; NV_NAME: LTPB071C125; PACK_TYPE: PIN; PATH: I160; PHYS_PAGE: 5; ROT: 0; SEC: 1; VER: 3; XY: (-2350,3900)
TP16 = LABTESTPOINT: CDS_LIB: electro_mechanic; CDS_PART_NAME: LABTESTPOINT_PIN-LTPB071C125; CDS_PHYS_PART_NAME: LABTESTPOINT_PIN-LTPB071C125; CDS_SEC: 1; DEVICE_TYPENAME: LABTESTPOINT_PIN-LTPB071C125; DRAWING: #NAME?; NV_NAME: LTPB071C125; PACK_TYPE: PIN; PATH: I161; PHYS_PAGE: 5; ROT: 0; SEC: 1; VER: 3; XY: (-2350,3800)
TP17 = LABTESTPOINT: CDS_LIB: electro_mechanic; CDS_PART_NAME: LABTESTPOINT_PIN-LTPB071C125; CDS_PHYS_PART_NAME: LABTESTPOINT_PIN-LTPB071C125; CDS_SEC: 1; DEVICE_TYPENAME: LABTESTPOINT_PIN-LTPB071C125; DRAWING: #NAME?; NV_NAME: LTPB071C125; PACK_TYPE: PIN; PATH: I162; PHYS_PAGE: 5; ROT: 0; SEC: 1; VER: 3; XY: (-2350,3700)
TP18 = LABTESTPOINT: CDS_LIB: electro_mechanic; CDS_PART_NAME: LABTESTPOINT_PIN-LTPB071C125; CDS_PHYS_PART_NAME: LABTESTPOINT_PIN-LTPB071C125; CDS_SEC: 1; DEVICE_TYPENAME: LABTESTPOINT_PIN-LTPB071C125; DRAWING: #NAME?; NV_NAME: LTPB071C125; PACK_TYPE: PIN; PATH: I163; PHYS_PAGE: 5; ROT: 0; SEC: 1; VER: 3; XY: (-2350,3600)
TP19 = LABTESTPOINT: CDS_LIB: electro_mechanic; CDS_PART_NAME: LABTESTPOINT_PIN-LTPB071C125; CDS_PHYS_PART_NAME: LABTESTPOINT_PIN-LTPB071C125; CDS_SEC: 1; DEVICE_TYPENAME: LABTESTPOINT_PIN-LTPB071C125; DRAWING: #NAME?; NV_NAME: LTPB071C125; PACK_TYPE: PIN; PATH: I164; PHYS_PAGE: 5; ROT: 0; SEC: 1; VER: 3; XY: (-2350,3500)
TP20 = LABTESTPOINT: CDS_LIB: electro_mechanic; CDS_PART_NAME: LABTESTPOINT_PIN-LTPB071C125; CDS_PHYS_PART_NAME: LABTESTPOINT_PIN-LTPB071C125; CDS_SEC: 1; DEVICE_TYPENAME: LABTESTPOINT_PIN-LTPB071C125; DRAWING: #NAME?; NV_NAME: LTPB071C125; PACK_TYPE: PIN; PATH: I165; PHYS_PAGE: 5; ROT: 0; SEC: 1; VER: 3; XY: (-2350,3400)
TP21 = LABTESTPOINT: CDS_LIB: electro_mechanic; CDS_PART_NAME: LABTESTPOINT_PIN-LTPB071C125; CDS_PHYS_PART_NAME: LABTESTPOINT_PIN-LTPB071C125; CDS_SEC: 1; DEVICE_TYPENAME: LABTESTPOINT_PIN-LTPB071C125; DRAWING: #NAME?; NV_NAME: LTPB071C125; PACK_TYPE: PIN; PATH: I166; PHYS_PAGE: 5; ROT: 0; SEC: 1; VER: 3; XY: (-2350,3300)
TP22 = LABTESTPOINT: CDS_LIB: electro_mechanic; CDS_PART_NAME: LABTESTPOINT_PIN-LTPB071C125; CDS_PHYS_PART_NAME: LABTESTPOINT_PIN-LTPB071C125; CDS_SEC: 1; DEVICE_TYPENAME: LABTESTPOINT_PIN-LTPB071C125; DRAWING: #NAME?; NV_NAME: LTPB071C125; PACK_TYPE: PIN; PATH: I167; PHYS_PAGE: 5; ROT: 0; SEC: 1; VER: 3; XY: (-2350,3200)
TP23 = LABTESTPOINT: CDS_LIB: electro_mechanic; CDS_PART_NAME: LABTESTPOINT_PIN-LTPB071C125; CDS_PHYS_PART_NAME: LABTESTPOINT_PIN-LTPB071C125; CDS_SEC: 1; DEVICE_TYPENAME: LABTESTPOINT_PIN-LTPB071C125; DRAWING: #NAME?; NV_NAME: LTPB071C125; PACK_TYPE: PIN; PATH: I168; PHYS_PAGE: 5; ROT: 0; SEC: 1; VER: 3; XY: (-2350,3100)
TP24 = LABTESTPOINT: CDS_LIB: electro_mechanic; CDS_PART_NAME: LABTESTPOINT_PIN-LTPB071C125; CDS_PHYS_PART_NAME: LABTESTPOINT_PIN-LTPB071C125; CDS_SEC: 1; DEVICE_TYPENAME: LABTESTPOINT_PIN-LTPB071C125; DRAWING: #NAME?; NV_NAME: LTPB071C125; PACK_TYPE: PIN; PATH: I169; PHYS_PAGE: 5; ROT: 0; SEC: 1; VER: 3; XY: (-2350,3000)
TP31 = LABTESTPOINT: CDS_LIB: electro_mechanic; CDS_PART_NAME: LABTESTPOINT_PIN-LTPB071C125; CDS_PHYS_PART_NAME: LABTESTPOINT_PIN-LTPB071C125; CDS_SEC: 1; DEVICE_TYPENAME: LABTESTPOINT_PIN-LTPB071C125; DRAWING: #NAME?; NV_NAME: LTPB071C125; PACK_TYPE: PIN; PATH: I182; PHYS_PAGE: 5; ROT: 0; SEC: 1; VER: 3; XY: (-2350,5850)
TP32 = LABTESTPOINT: CDS_LIB: electro_mechanic; CDS_PART_NAME: LABTESTPOINT_PIN-LTPB071C125; CDS_PHYS_PART_NAME: LABTESTPOINT_PIN-LTPB071C125; CDS_SEC: 1; DEVICE_TYPENAME: LABTESTPOINT_PIN-LTPB071C125; DRAWING: #NAME?; NV_NAME: LTPB071C125; PACK_TYPE: PIN; PATH: I177; PHYS_PAGE: 5; ROT: 0; SEC: 1; VER: 3; XY: (-2350,5750)
TP33 = LABTESTPOINT: CDS_LIB: electro_mechanic; CDS_PART_NAME: LABTESTPOINT_PIN-LTPB071C125; CDS_PHYS_PART_NAME: LABTESTPOINT_PIN-LTPB071C125; CDS_SEC: 1; DEVICE_TYPENAME: LABTESTPOINT_PIN-LTPB071C125; DRAWING: #NAME?; NV_NAME: LTPB071C125; PACK_TYPE: PIN; PATH: I178; PHYS_PAGE: 5; ROT: 0; SEC: 1; VER: 3; XY: (-2350,5650)
TP34 = LABTESTPOINT: CDS_LIB: electro_mechanic; CDS_PART_NAME: LABTESTPOINT_PIN-LTPB071C125; CDS_PHYS_PART_NAME: LABTESTPOINT_PIN-LTPB071C125; CDS_SEC: 1; DEVICE_TYPENAME: LABTESTPOINT_PIN-LTPB071C125; DRAWING: #NAME?; NV_NAME: LTPB071C125; PACK_TYPE: PIN; PATH: I179; PHYS_PAGE: 5; ROT: 0; SEC: 1; VER: 3; XY: (-2350,5550)
TP35 = LABTESTPOINT: CDS_LIB: electro_mechanic; CDS_PART_NAME: LABTESTPOINT_PIN-LTPB071C125; CDS_PHYS_PART_NAME: LABTESTPOINT_PIN-LTPB071C125; CDS_SEC: 1; DEVICE_TYPENAME: LABTESTPOINT_PIN-LTPB071C125; DRAWING: #NAME?; NV_NAME: LTPB071C125; PACK_TYPE: PIN; PATH: I180; PHYS_PAGE: 5; ROT: 0; SEC: 1; VER: 3; XY: (-2350,5450)
TP36 = LABTESTPOINT: CDS_LIB: electro_mechanic; CDS_PART_NAME: LABTESTPOINT_PIN-LTPB071C125; CDS_PHYS_PART_NAME: LABTESTPOINT_PIN-LTPB071C125; CDS_SEC: 1; DEVICE_TYPENAME: LABTESTPOINT_PIN-LTPB071C125; DRAWING: #NAME?; NV_NAME: LTPB071C125; PACK_TYPE: PIN; PATH: I181; PHYS_PAGE: 5; ROT: 0; SEC: 1; VER: 3; XY: (-2350,5350)
TP37 = LABTESTPOINT: CDS_LIB: electro_mechanic; CDS_PART_NAME: LABTESTPOINT_PIN-LTPB071C125; CDS_PHYS_PART_NAME: LABTESTPOINT_PIN-LTPB071C125; CDS_SEC: 1; DEVICE_TYPENAME: LABTESTPOINT_PIN-LTPB071C125; DRAWING: #NAME?; NV_NAME: LTPB071C125; PACK_TYPE: PIN; PATH: I175; PHYS_PAGE: 5; ROT: 0; SEC: 1; VER: 3; XY: (-2350,4550)
TP38 = LABTESTPOINT: CDS_LIB: electro_mechanic; CDS_PART_NAME: LABTESTPOINT_PIN-LTPB071C125; CDS_PHYS_PART_NAME: LABTESTPOINT_PIN-LTPB071C125; CDS_SEC: 1; DEVICE_TYPENAME: LABTESTPOINT_PIN-LTPB071C125; DRAWING: #NAME?; NV_NAME: LTPB071C125; PACK_TYPE: PIN; PATH: I176; PHYS_PAGE: 5; ROT: 0; SEC: 1; VER: 3; XY: (-2350,4450)
TP39 = LABTESTPOINT: CDS_LIB: electro_mechanic; CDS_PART_NAME: LABTESTPOINT_PIN-LTPB071C125; CDS_PHYS_PART_NAME: LABTESTPOINT_PIN-LTPB071C125; CDS_SEC: 1; DEVICE_TYPENAME: LABTESTPOINT_PIN-LTPB071C125; DRAWING: #NAME?; NV_NAME: LTPB071C125; PACK_TYPE: PIN; PATH: I171; PHYS_PAGE: 5; ROT: 0; SEC: 1; VER: 3; XY: (-2350,4350)
TP40 = LABTESTPOINT: CDS_LIB: electro_mechanic; CDS_PART_NAME: LABTESTPOINT_PIN-LTPB071C125; CDS_PHYS_PART_NAME: LABTESTPOINT_PIN-LTPB071C125; CDS_SEC: 1; DEVICE_TYPENAME: LABTESTPOINT_PIN-LTPB071C125; DRAWING: #NAME?; NV_NAME: LTPB071C125; PACK_TYPE: PIN; PATH: I172; PHYS_PAGE: 5; ROT: 0; SEC: 1; VER: 3; XY: (-2350,4250)
TP41 = LABTESTPOINT: CDS_LIB: electro_mechanic; CDS_PART_NAME: LABTESTPOINT_PIN-LTPB071C125; CDS_PHYS_PART_NAME: LABTESTPOINT_PIN-LTPB071C125; CDS_SEC: 1; DEVICE_TYPENAME: LABTESTPOINT_PIN-LTPB071C125; DRAWING: #NAME?; NV_NAME: LTPB071C125; PACK_TYPE: PIN; PATH: I173; PHYS_PAGE: 5; ROT: 0; SEC: 1; VER: 3; XY: (-2350,4150)
TP42 = LABTESTPOINT: CDS_LIB: electro_mechanic; CDS_PART_NAME: LABTESTPOINT_PIN-LTPB071C125; CDS_PHYS_PART_NAME: LABTESTPOINT_PIN-LTPB071C125; CDS_SEC: 1; DEVICE_TYPENAME: LABTESTPOINT_PIN-LTPB071C125; DRAWING: #NAME?; NV_NAME: LTPB071C125; PACK_TYPE: PIN; PATH: I174; PHYS_PAGE: 5; ROT: 0; SEC: 1; VER: 3; XY: (-2350,4050)

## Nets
GND: C145.2 C146.2 C147.2 D1.2 D2.2 D3.2 J2.1(GND1) J2.2(GND2) J2.7(GND3) J2.8(GND4) J2.13(GND5) J2.14(GND6) J2.19(GND7) J2.20(GND8) J2.25(GND9) J2.26(GND10) J2.31(GND11) J2.32(GND12) J2.37(GND13) J2.38(GND14) J2.43(GND15) J2.44(GND16) J2.49(GND17) J2.50(GND18) J2.55(GND19) J2.56(GND20) J2.61(GND21) J2.62(GND22) J2.67(GND23) J2.68(GND24) J2.73(GND25) J2.74(GND26) J2.79(GND27) J2.80(GND28) J2.85(GND29) J2.86(GND30) J2.102(GND31) J2.107(GND32) J2.113(GND33) J2.119(GND34) J2.125(GND35) J2.129(GND36) J2.132(GND37) J2.135(GND38) J2.138(GND39) J2.141(GND40) J2.144(GND41) J2.146(GND42) J2.147(GND43) J2.152(GND44) J2.153(GND45) J2.158(GND46) J2.159(GND47) J2.164(GND48) J2.165(GND49) J2.170(GND50) J2.171(GND51) J2.176(GND52) J2.177(GND53) J2.200(GND54) J2.201(GND55) J2.217(GND56) J2.231(GND57) J2.241(GND58) J2.242(GND59) J2.243(GND60) J2.244(GND61) J2.245(GND62) J2.246(GND63) J2.247(GND64) J2.248(GND65) J2.249(GND66) J2.250(GND67) J2.261(MNT1) J2.262(MNT2) J3.2 J17.3 Q1.2(S) ; also on sheet 1 2 3 4 5 6 7 8 9 10 11 12 13 14 15 16 17 18 19
VDD_1V8: R5.1 R6.1 ; also on sheet 2 3 4 5 8 9 15 19
VDD_3V3_SYS: J17.4 R3.1 R4.1 R8.1 R10.1 R11.1 R12.1 ; also on sheet 2 3 4 5 6 7 8 9 12 15 16 19
VDD_5V_SYS: C145.1 C146.1 C147.1 DS1.1(A) J2.251(VDD_IN1) J2.252(VDD_IN2) J2.253(VDD_IN3) J2.254(VDD_IN4) J2.255(VDD_IN5) J2.256(VDD_IN6) J2.257(VDD_IN7) J2.258(VDD_IN8) J2.259(VDD_IN9) J2.260(VDD_IN10) R9.1 ; also on sheet 2 3 8 9 10 11 12 14 15 16 17
BBAT: D4.1(K) J2.235(PMIC_BBAT) R222.1
BBAT_CONN: D4.2(A) J3.1 J3.3 R222.2
BT_M2_EN: J2.126(GPS_EN) ; also on sheet 5
BT_M2_WAKE_AP: J2.124(GPIO_PH6) ; also on sheet 5
CAM0_MCLK: J2.116(CAM1_MCLK) ; also on sheet 7
CAM0_PWDN: J2.114(CAM1_PWDN) ; also on sheet 7
CAM1_MCLK: J2.122(CAM2_MCLK) ; also on sheet 7
CAM1_PWDN: J2.120(CAM2_PWDN) ; also on sheet 7
CAM_I2C_SCL: J2.213(CAM_I2C_SCL) R11.2 ; also on sheet 7 12
CAM_I2C_SDA: J2.215(CAM_I2C_SDA) R12.2 ; also on sheet 7 12
CAM_MUX_SEL: J2.130(NFC_EN) ; also on sheet 7
CAN_RX: J2.143(CAN_RX) J17.2
CAN_TX: J2.145(CAN_TX) J17.1
CSI0_CLK_N: J2.10(CSI_A_CLK_N) ; also on sheet 7
CSI0_CLK_P: J2.12(CSI_A_CLK_P) ; also on sheet 7
CSI0_D0_N: J2.4(CSI_A_D0_N) ; also on sheet 7
CSI0_D0_P: J2.6(CSI_A_D0_P) ; also on sheet 7
CSI0_D1_N: J2.16(CSI_A_D1_N) ; also on sheet 7
CSI0_D1_P: J2.18(CSI_A_D1_P) ; also on sheet 7
CSI1_CLK_N: J2.9(CSI_B_CLK_N) TP36.1
CSI1_CLK_P: J2.11(CSI_B_CLK_P) TP35.1
CSI1_D0_N: J2.3(CSI_B_D0_N) TP32.1
CSI1_D0_P: J2.5(CSI_B_D0_P) TP31.1
CSI1_D1_N: J2.15(CSI_B_D1_N) TP34.1
CSI1_D1_P: J2.17(CSI_B_D1_P) TP33.1
CSI2_CLK_N: J2.28(CSI_E_CLK_N) ; also on sheet 7
CSI2_CLK_P: J2.30(CSI_E_CLK_P) ; also on sheet 7
CSI2_D0_N: J2.22(CSI_E_D0_N) ; also on sheet 7
CSI2_D0_P: J2.24(CSI_E_D0_P) ; also on sheet 7
CSI2_D1_N: J2.34(CSI_E_D1_N) ; also on sheet 7
CSI2_D1_P: J2.36(CSI_E_D1_P) ; also on sheet 7
CSI3_CLK_N: J2.27(CSI_F_CLK_N) TP42.1
CSI3_CLK_P: J2.29(CSI_F_CLK_P) TP41.1
CSI3_D0_N: J2.21(CSI_F_D0_N) TP38.1
CSI3_D0_P: J2.23(CSI_F_D0_P) TP37.1
CSI3_D1_N: J2.33(CSI_F_D1_N) TP40.1
CSI3_D1_P: J2.35(CSI_F_D1_P) TP39.1
CSI4_CLK_N: J2.52(CSI_C_CLK_N) TP20.1
CSI4_CLK_P: J2.54(CSI_C_CLK_P) TP19.1
CSI4_D0_N: J2.46(CSI_C_D0_N) TP18.1
CSI4_D0_P: J2.48(CSI_C_D0_P) TP17.1
CSI4_D1_N: J2.58(CSI_C_D1_N) TP22.1
CSI4_D1_P: J2.60(CSI_C_D1_P) TP21.1
CSI4_D2_N: J2.40(CSI_D_D0_N) TP16.1
CSI4_D2_P: J2.42(CSI_D_D0_P) TP15.1
CSI4_D3_N: J2.64(CSI_D_D1_N) TP24.1
CSI4_D3_P: J2.66(CSI_D_D1_P) TP23.1
FAN_PWM: J2.230(GPIO_PE7) ; also on sheet 2
FAN_TACH: J2.208(GPIO_PZ2) ; also on sheet 2
FORCE_RECOVERY*: D2.1 J2.214(FORCE_RECOVERY*) ; also on sheet 2
GBE_LED_ACT: J2.194(GBE_LED1) ; also on sheet 6
GBE_LED_LINK: J2.188(GBE_LED0) ; also on sheet 6
GBE_MDI0_N: J2.184(GBE_MDI0_N) ; also on sheet 6
GBE_MDI0_P: J2.186(GBE_MDI0_P) ; also on sheet 6
GBE_MDI1_N: J2.190(GBE_MDI1_N) ; also on sheet 6
GBE_MDI1_P: J2.192(GBE_MDI1_P) ; also on sheet 6
GBE_MDI2_N: J2.196(GBE_MDI2_N) ; also on sheet 6
GBE_MDI2_P: J2.198(GBE_MDI2_P) ; also on sheet 6
GBE_MDI3_N: J2.202(GBE_MDI3_N) ; also on sheet 6
GBE_MDI3_P: J2.204(GBE_MDI3_P) ; also on sheet 6
GPIO01: J2.118(CAM_AF_EN) ; also on sheet 3
GPIO07: J2.206(LCD_BL_PWM) ; also on sheet 3
GPIO09: J2.211(AUD_MCLK) ; also on sheet 3
GPIO11: J2.216(GPIO_PZ0) ; also on sheet 3
GPIO12: J2.218(LCD_TE) ; also on sheet 3
GPIO13: J2.228(GPIO_PE6) ; also on sheet 3
I2C1_SCL: J2.189(GEN2_I2C_SCL) R8.2 ; also on sheet 3
I2C1_SDA: J2.191(GEN2_I2C_SDA) R10.2 ; also on sheet 3
I2C2_SCL: J2.232(GEN3_I2C_SCL) R6.2 ; also on sheet 2 4 5
I2C2_SDA: J2.234(GEN3_I2C_SDA) R5.2 ; also on sheet 2 4 5
I2S0_LRCK: J2.197(DAP4_FS) ; also on sheet 3
I2S0_SCLK: J2.199(DAP4_SCLK) ; also on sheet 3
I2S0_SDIN: J2.195(DAP4_DIN) ; also on sheet 3
I2S0_SDOUT: J2.193(DAP4_DOUT) ; also on sheet 3
I2S1_LRCK: J2.224(DAP3_FS) ; also on sheet 5
I2S1_SCLK: J2.226(DAP3_SCLK) ; also on sheet 5
I2S1_SDIN: J2.222(DAP3_DIN) ; also on sheet 5
I2S1_SDOUT: J2.220(DAP3_DOUT) ; also on sheet 5
ID_I2C_SCL: J2.185(GEN1_I2C_SCL) R3.2 ; also on sheet 3
ID_I2C_SDA: J2.187(GEN1_I2C_SDA) R4.2 ; also on sheet 3
LED0_CTRL: Q1.1(G) R1.2 R2.2
M2_SDIO_D1: R186.1 ; also on sheet 5
M2E_ALERT*: J2.212(LCD_BL_EN) ; also on sheet 5
M2M_ALERT*: R185.1 ; also on sheet 4
MOD_SLEEP*: J2.178(GPIO_PA6) R2.1 ; also on sheet 2 9
POWER_EN: J2.237(POWER_EN) ; also on sheet 8 14
PWR_BTN*: D3.1 J2.240(BUTTON_PWR_ON*) R9.2 ; also on sheet 2 14
PWR_LED: DS1.2(K) R7.1
PWR_LED_CTRL: J2.127(NFC_INT) R1.1 ; also on sheet 2
PWR_LED_R: Q1.3(D) R7.2
SDIO_CLK: J2.229(SDMMC3_CLK) ; also on sheet 5
SDIO_CMD: J2.227(SDMMC3_CMD) ; also on sheet 5
SDIO_D0: J2.219(SDMMC3_DAT0) ; also on sheet 5
SDIO_D1: J2.221(SDMMC3_DAT1) R185.2 R186.2
SDIO_D2: J2.223(SDMMC3_DAT2) ; also on sheet 5
SDIO_D3: J2.225(SDMMC3_DAT3) ; also on sheet 5
SHUTDOWN_REQ*: J2.233(SHUTDOWN_REQ*) ; also on sheet 14 18
SPI0_CS0: J2.95(SPI1_CS0) ; also on sheet 3
SPI0_CS1: J2.97(SPI1_CS1) ; also on sheet 3
SPI0_MISO: J2.93(SPI1_MISO) ; also on sheet 3
SPI0_MOSI: J2.89(SPI1_MOSI) ; also on sheet 3
SPI0_SCK: J2.91(SPI1_SCK) ; also on sheet 3
SPI1_CS0: J2.110(SPI2_CS0) ; also on sheet 3
SPI1_CS1: J2.112(SPI2_CS1) ; also on sheet 3
SPI1_MISO: J2.108(SPI2_MISO) ; also on sheet 3
SPI1_MOSI: J2.104(SPI2_MOSI) ; also on sheet 3
SPI1_SCK: J2.106(SPI2_SCK) ; also on sheet 3
SYS_RST*: D1.1 J2.239(SYS_RESET_IN*) ; also on sheet 2 14
UART0_CTS: J2.105(UART3_CTS) ; also on sheet 5
UART0_RTS: J2.103(UART3_RTS) ; also on sheet 5
UART0_RXD: J2.101(UART3_RXD) ; also on sheet 5
UART0_TXD: J2.99(UART3_TXD) ; also on sheet 5
UART1_CTS: J2.209(UART2_CTS) ; also on sheet 3
UART1_RTS: J2.207(UART2_RTS) ; also on sheet 3
UART1_RXD: J2.205(UART2_RXD) ; also on sheet 3
UART1_TXD: J2.203(UART2_TXD) ; also on sheet 3
UART2_RXD: J2.238(UART1_RXD) ; also on sheet 2
UART2_TXD: J2.236(UART1_TXD) ; also on sheet 2
USB0_AP_N: J2.109(USB0_DN) ; also on sheet 13
USB0_AP_P: J2.111(USB0_DP) ; also on sheet 13
USB0_VBUS_DET*: J2.87(USB_VBUS_EN0) ; also on sheet 13
USB1_AP_N: J2.115(USB1_DN) ; also on sheet 12
USB1_AP_P: J2.117(USB1_DP) ; also on sheet 12
USB2_AP_N: J2.121(USB2_DN) ; also on sheet 5
USB2_AP_P: J2.123(USB2_DP) ; also on sheet 5
W_DISABLE1_CTRL: J2.128(AP_WAKE_NFC) ; also on sheet 5

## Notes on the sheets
sheet 20
- A
- B
- C
- D
- E
- F
- G
- H
- GPIOs, USB2.0, I2S, SPI, GBe and CSI
- 1
- 1
- uUSB Con
- CAM FPC Con
- USB Type-A Con
- M.2 BT
- PUT TESTPOINT
- ON BOTTOM OF
- 40Pin GPIO HDR
- PCB
- 2
- 2
- M.2 BT
- CAM FPC Con
- ETHERNET CON
- PUT TESTPOINT
- ON BOTTOM OF
- PCB
- 3
- 3
- M.2 KEY-E
- DFT
- PCB CO-LAYOUT
- CAM FPC Con
- 4
- USB3.1 HUB
- 4
- 40Pin GPIO HDR
- 5
- 5
- NVIDIA CORPORATION
- 2701 SAN TOMAS
  EXPRESSWAY
- ASSEMBLY
- <ASSEMBLY_DESCRIPTION>
- SANTA CLARA, CA 95050, USA
- PAGE DETAIL
- SODIMM Connector 2/3
- NV_PN
- 600-13509-BASE-100
- ALL NVIDIA DESIGN SPECIFICATIONS, REFERENCE SPECIFICATIONS, REFERENCE BOARDS, FILES, DRAWINGS, DIAGNOSTICS, LISTS AND OTHER DOCUMENTS OR INFORMATION (TOGETHER AND SEPARATELY, 'MATERIALS') ARE BEING PROVIDED 'AS IS'. THE MATERIALS
  MAY
- CONTAIN KNOWN AND UNKNOWN VIOLATIONS OR DEVIATIONS OF INDUSTRY STANDARDS AND SPECIFICATIONS. NVIDIA MAKES NO WARRANTIES, EXPRESSED, IMPLIED, STATUTORY OR OTHERWISE WITH RESPECT TO THE MATERIALS OR OTHERWISE, AND EXPRESSLY DISCLAIMS
  ALL
- PCB REV
- P3509-A01
- PAGE
- 5 OF 25
- IMPLIED WARRANTIES INCLUDING, WITHOUT LIMITATION, THE WARRANTIES OF DESIGN, OF NONINFRINGEMENT, MERCHANTABILITY OR FITNESS FOR A PARTICULAR PURPOSE, OR ARISING FROM A COURSE OF DEALING, TRADE USAGE, TRADE PRACTICE, OR INDUSTRY
  STANDARDS.
- BOM REV
- <BOM_REV>
- DATE
- 27-NOV-2019
- A
- B
- C
- D
- E
- F
- G
- H
sheet 21
- A
- B
- C
- D
- E
- F
- G
- H
- UART, I2C, CAN and GPIOs
- I2C PULL-UP
- 1
- 1
- NO STUFF THESE
- M.2 WIFI/BT
- 2
- 2
- 40PIN GPIO EXPANSION HEADER
- DEBUG
- PULL-UP FOR POWER BUTTON
- 3
- 3
- PLACE J45 ON BACK
- OF PCB
- COIN CELL: CR1225
- POWER LED
- 4
- 4
- CAN BUS
- 5
- 5
- NVIDIA CORPORATION
- 2701 SAN TOMAS EXPRESSWAY
- ASSEMBLY
- <ASSEMBLY_DESCRIPTION>
- SANTA CLARA, CA 95050, USA
- PAGE DETAIL
- SODIMM Connector 1/3
- NV_PN
- 600-13509-BASE-100
- ALL NVIDIA DESIGN SPECIFICATIONS, REFERENCE SPECIFICATIONS, REFERENCE BOARDS, FILES, DRAWINGS, DIAGNOSTICS, LISTS AND OTHER DOCUMENTS OR INFORMATION (TOGETHER AND SEPARATELY, 'MATERIALS') ARE BEING PROVIDED 'AS IS'. THE MATERIALS MAY
- CONTAIN KNOWN AND UNKNOWN VIOLATIONS OR DEVIATIONS OF INDUSTRY STANDARDS AND SPECIFICATIONS. NVIDIA MAKES NO WARRANTIES, EXPRESSED, IMPLIED, STATUTORY OR OTHERWISE WITH RESPECT TO THE MATERIALS OR OTHERWISE, AND EXPRESSLY DISCLAIMS ALL
- PCB REV
- P3509-A01
- PAGE
- 4 OF 25
- IMPLIED WARRANTIES INCLUDING, WITHOUT LIMITATION, THE WARRANTIES OF DESIGN, OF NONINFRINGEMENT, MERCHANTABILITY OR FITNESS FOR A PARTICULAR PURPOSE, OR ARISING FROM A COURSE OF DEALING, TRADE USAGE, TRADE PRACTICE, OR INDUSTRY STANDARDS.
- BOM REV
- <BOM_REV>
- DATE
- 27-NOV-2019
- A
- B
- C
- D
- E
- F
- G
- H
sheet 22
- A
- B
- C
- D
- E
- F
- G
- H
- 1
- 1
- 2
- 2
- $CDS_IMAGE|Power_tree_4_0.jpg|10902|6562
- 3
- 3
- 4
- 4
- 5
- 5
- NVIDIA CORPORATION
- 2701 SAN TOMAS
  EXPRESSWAY
- ASSEMBLY
- <ASSEMBLY_DESCRIPTION>
- SANTA CLARA, CA 95050, USA
- PAGE DETAIL
- Power
  Tree
- NV_PN
- 600-13509-BASE-100
- ALL NVIDIA DESIGN SPECIFICATIONS, REFERENCE SPECIFICATIONS, REFERENCE BOARDS, FILES, DRAWINGS, DIAGNOSTICS, LISTS AND OTHER DOCUMENTS OR INFORMATION (TOGETHER AND SEPARATELY, 'MATERIALS') ARE BEING PROVIDED 'AS IS'. THE MATERIALS
  MAY
- CONTAIN KNOWN AND UNKNOWN VIOLATIONS OR DEVIATIONS OF INDUSTRY STANDARDS AND SPECIFICATIONS. NVIDIA MAKES NO WARRANTIES, EXPRESSED, IMPLIED, STATUTORY OR OTHERWISE WITH RESPECT TO THE MATERIALS OR OTHERWISE, AND EXPRESSLY DISCLAIMS
  ALL
- PCB REV
- P3509-A01
- PAGE
- 3 OF 25
- IMPLIED WARRANTIES INCLUDING, WITHOUT LIMITATION, THE WARRANTIES OF DESIGN, OF NONINFRINGEMENT, MERCHANTABILITY OR FITNESS FOR A PARTICULAR PURPOSE, OR ARISING FROM A COURSE OF DEALING, TRADE USAGE, TRADE PRACTICE, OR INDUSTRY
  STANDARDS.
- BOM REV
- <BOM_REV>
- DATE
- 27-NOV-2019
- A
- B
- C
- D
- E
- F
- G
- H
sheet 23
- A
- B
- C
- D
- E
- F
- G
- H
- 1
- 1
- 2
- 2
- 3
- 3
- 4
- 4
- 5
- 5
- NVIDIA CORPORATION
- 2701 SAN TOMAS
  EXPRESSWAY
- ASSEMBLY
- <ASSEMBLY_DESCRIPTION>
- SANTA CLARA, CA 95050, USA
- PAGE DETAIL
- Block
  Diagram
- NV_PN
- 600-13509-BASE-100
- ALL NVIDIA DESIGN SPECIFICATIONS, REFERENCE SPECIFICATIONS, REFERENCE BOARDS, FILES, DRAWINGS, DIAGNOSTICS, LISTS AND OTHER DOCUMENTS OR INFORMATION (TOGETHER AND SEPARATELY, 'MATERIALS') ARE BEING PROVIDED 'AS IS'. THE MATERIALS
  MAY
- CONTAIN KNOWN AND UNKNOWN VIOLATIONS OR DEVIATIONS OF INDUSTRY STANDARDS AND SPECIFICATIONS. NVIDIA MAKES NO WARRANTIES, EXPRESSED, IMPLIED, STATUTORY OR OTHERWISE WITH RESPECT TO THE MATERIALS OR OTHERWISE, AND EXPRESSLY DISCLAIMS
  ALL
- PCB REV
- P3509-A01
- PAGE
- 2 OF 25
- IMPLIED WARRANTIES INCLUDING, WITHOUT LIMITATION, THE WARRANTIES OF DESIGN, OF NONINFRINGEMENT, MERCHANTABILITY OR FITNESS FOR A PARTICULAR PURPOSE, OR ARISING FROM A COURSE OF DEALING, TRADE USAGE, TRADE PRACTICE, OR INDUSTRY
  STANDARDS.
- BOM REV
- <BOM_REV>
- DATE
- 27-NOV-2019
- A
- B
- C
- D
- E
- F
- G
- H
sheet 24
- A
- B
- C
- D
- E
- F
- G
- H
- P3509-A01
- Jetson Xavier NX Carrier Board
- HDMI, DP, USB3.1, M.2 Key-E & M, GBe, CAM
- 1
- 1
- TABLE OF CONTENTS
- Page
- Description
- 1
- Table of Contents
- 2
- Block Diagram
- 3
- Power Tree
- 4
- SODIMM Connector 1/3
- 5
- SODIMM Connector 2/3
- 2
- 2
- 6
- SODIMM Connector 3/3
- 7
- DC_JACK
- 8
- PRE-REG 5V
- 9
- PRE-REG 3V3
- 10
- 1V8 LDO & 3V3 AO Rails
- 11
- BUTTON MCU
- 12
- MICRO USB2.0
- 13
- USB3.1 HUB
- 14
- USB3.1 Type-A x2 (A)
- 15
- USB3.1 Type-A x2 (B)
- 3
- 3
- 16
- HDMI
- 17
- DISPLAY PORT
- 18
- CAMERA
- 19
- ETHERNET
- 20
- M.2 KEY-E (WIFI/BT)
- 21
- M.2 KEY-M (NVME)
- 22
- 40PIN GPIO Expansion HDR
- 23
- FAN, DEBUG and EEPROM
- 24
- MECHANICAL
- 25
- REVISION HISTORY
- 4
- 4
- 5
- 5
- NVIDIA CORPORATION
- 2701 SAN TOMAS EXPRESSWAY
- ASSEMBLY
- <ASSEMBLY_DESCRIPTION>
- SANTA CLARA, CA 95050, USA
- PAGE DETAIL
- Table of Contents
- NV_PN
- 600-13509-BASE-100
- ALL NVIDIA DESIGN SPECIFICATIONS, REFERENCE SPECIFICATIONS, REFERENCE BOARDS, FILES, DRAWINGS, DIAGNOSTICS, LISTS AND OTHER DOCUMENTS OR INFORMATION (TOGETHER AND SEPARATELY, 'MATERIALS') ARE BEING PROVIDED 'AS IS'. THE MATERIALS MAY
- CONTAIN KNOWN AND UNKNOWN VIOLATIONS OR DEVIATIONS OF INDUSTRY STANDARDS AND SPECIFICATIONS. NVIDIA MAKES NO WARRANTIES, EXPRESSED, IMPLIED, STATUTORY OR OTHERWISE WITH RESPECT TO THE MATERIALS OR OTHERWISE, AND EXPRESSLY DISCLAIMS ALL
- PCB REV
- P3509-A01
- PAGE
- 1 OF 25
- IMPLIED WARRANTIES INCLUDING, WITHOUT LIMITATION, THE WARRANTIES OF DESIGN, OF NONINFRINGEMENT, MERCHANTABILITY OR FITNESS FOR A PARTICULAR PURPOSE, OR ARISING FROM A COURSE OF DEALING, TRADE USAGE, TRADE PRACTICE, OR INDUSTRY STANDARDS.
- BOM REV
- <BOM_REV>
- DATE
- 27-NOV-2019
- A
- B
- C
- D
- E
- F
- G
- H
sheet 25
- A
- B
- C
- D
- E
- F
- G
- H
- REVISION HISTORY
- 1
- 1
- 2
- 2
- 3
- 3
- 4
- 4
- 5
- 5
- NVIDIA CORPORATION
- 2701 SAN TOMAS
  EXPRESSWAY
- ASSEMBLY
- <ASSEMBLY_DESCRIPTION>
- SANTA CLARA, CA 95050, USA
- PAGE DETAIL
- REVISION HISTORY
- NV_PN
- 600-13509-BASE-100
- ALL NVIDIA DESIGN SPECIFICATIONS, REFERENCE SPECIFICATIONS, REFERENCE BOARDS, FILES, DRAWINGS, DIAGNOSTICS, LISTS AND OTHER DOCUMENTS OR INFORMATION (TOGETHER AND SEPARATELY, 'MATERIALS') ARE BEING PROVIDED 'AS IS'. THE MATERIALS
  MAY
- CONTAIN KNOWN AND UNKNOWN VIOLATIONS OR DEVIATIONS OF INDUSTRY STANDARDS AND SPECIFICATIONS. NVIDIA MAKES NO WARRANTIES, EXPRESSED, IMPLIED, STATUTORY OR OTHERWISE WITH RESPECT TO THE MATERIALS OR OTHERWISE, AND EXPRESSLY DISCLAIMS
  ALL
- PCB REV
- P3509-A01
- PAGE
- 25 OF 25
- IMPLIED WARRANTIES INCLUDING, WITHOUT LIMITATION, THE WARRANTIES OF DESIGN, OF NONINFRINGEMENT, MERCHANTABILITY OR FITNESS FOR A PARTICULAR PURPOSE, OR ARISING FROM A COURSE OF DEALING, TRADE USAGE, TRADE PRACTICE, OR INDUSTRY
  STANDARDS.
- BOM REV
- <BOM_REV>
- DATE
- 27-NOV-2019
- A
- B
- C
- D
- E
- F
- G
- H
